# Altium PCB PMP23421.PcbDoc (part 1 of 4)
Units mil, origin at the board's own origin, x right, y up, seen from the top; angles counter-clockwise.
Board outline 2755.91 x 7559.06 mil, 8 copper layers (Top Layer, Signal Layer 1, Signal Layer 2, Signal Layer 3, Signal Layer 4, Signal Layer 5, Signal Layer 6, Bottom Layer), stack 60.4 mil thick; 211 components, 135 nets, 708 pads, 652 vias.
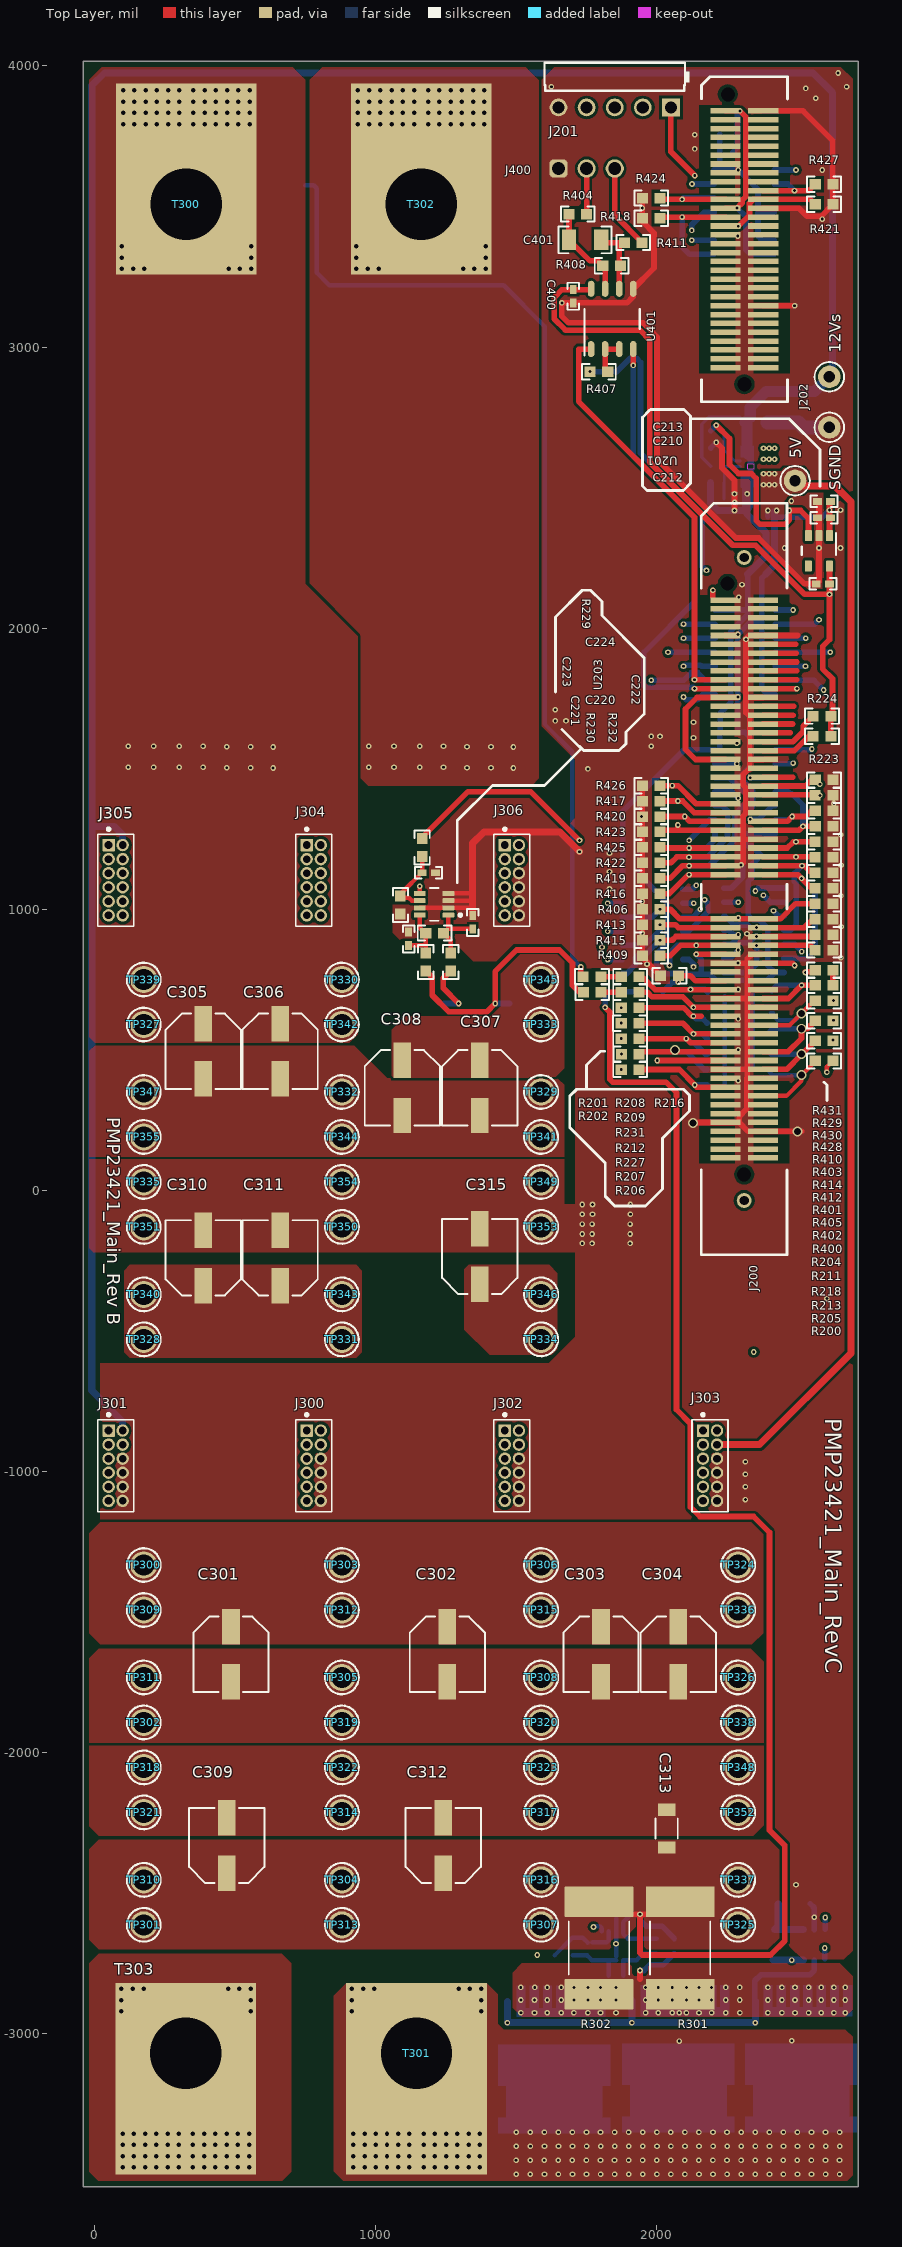
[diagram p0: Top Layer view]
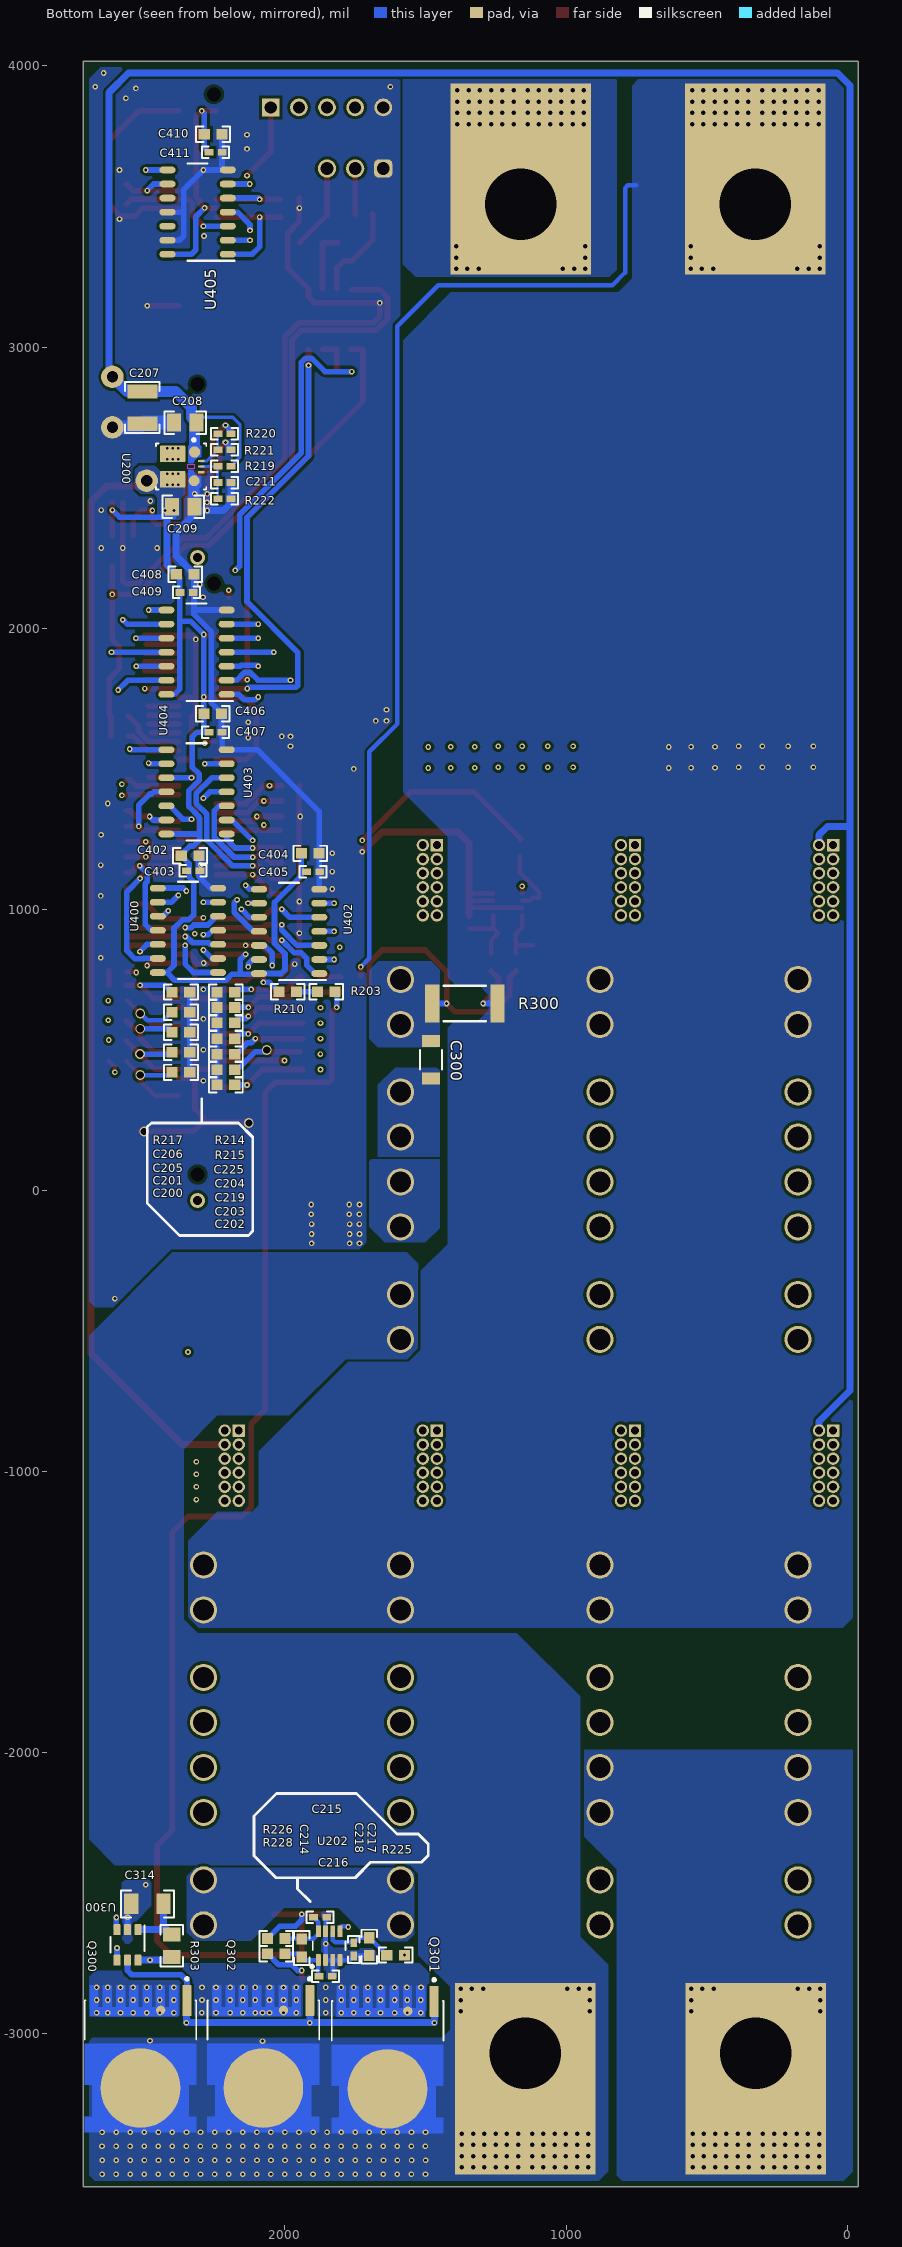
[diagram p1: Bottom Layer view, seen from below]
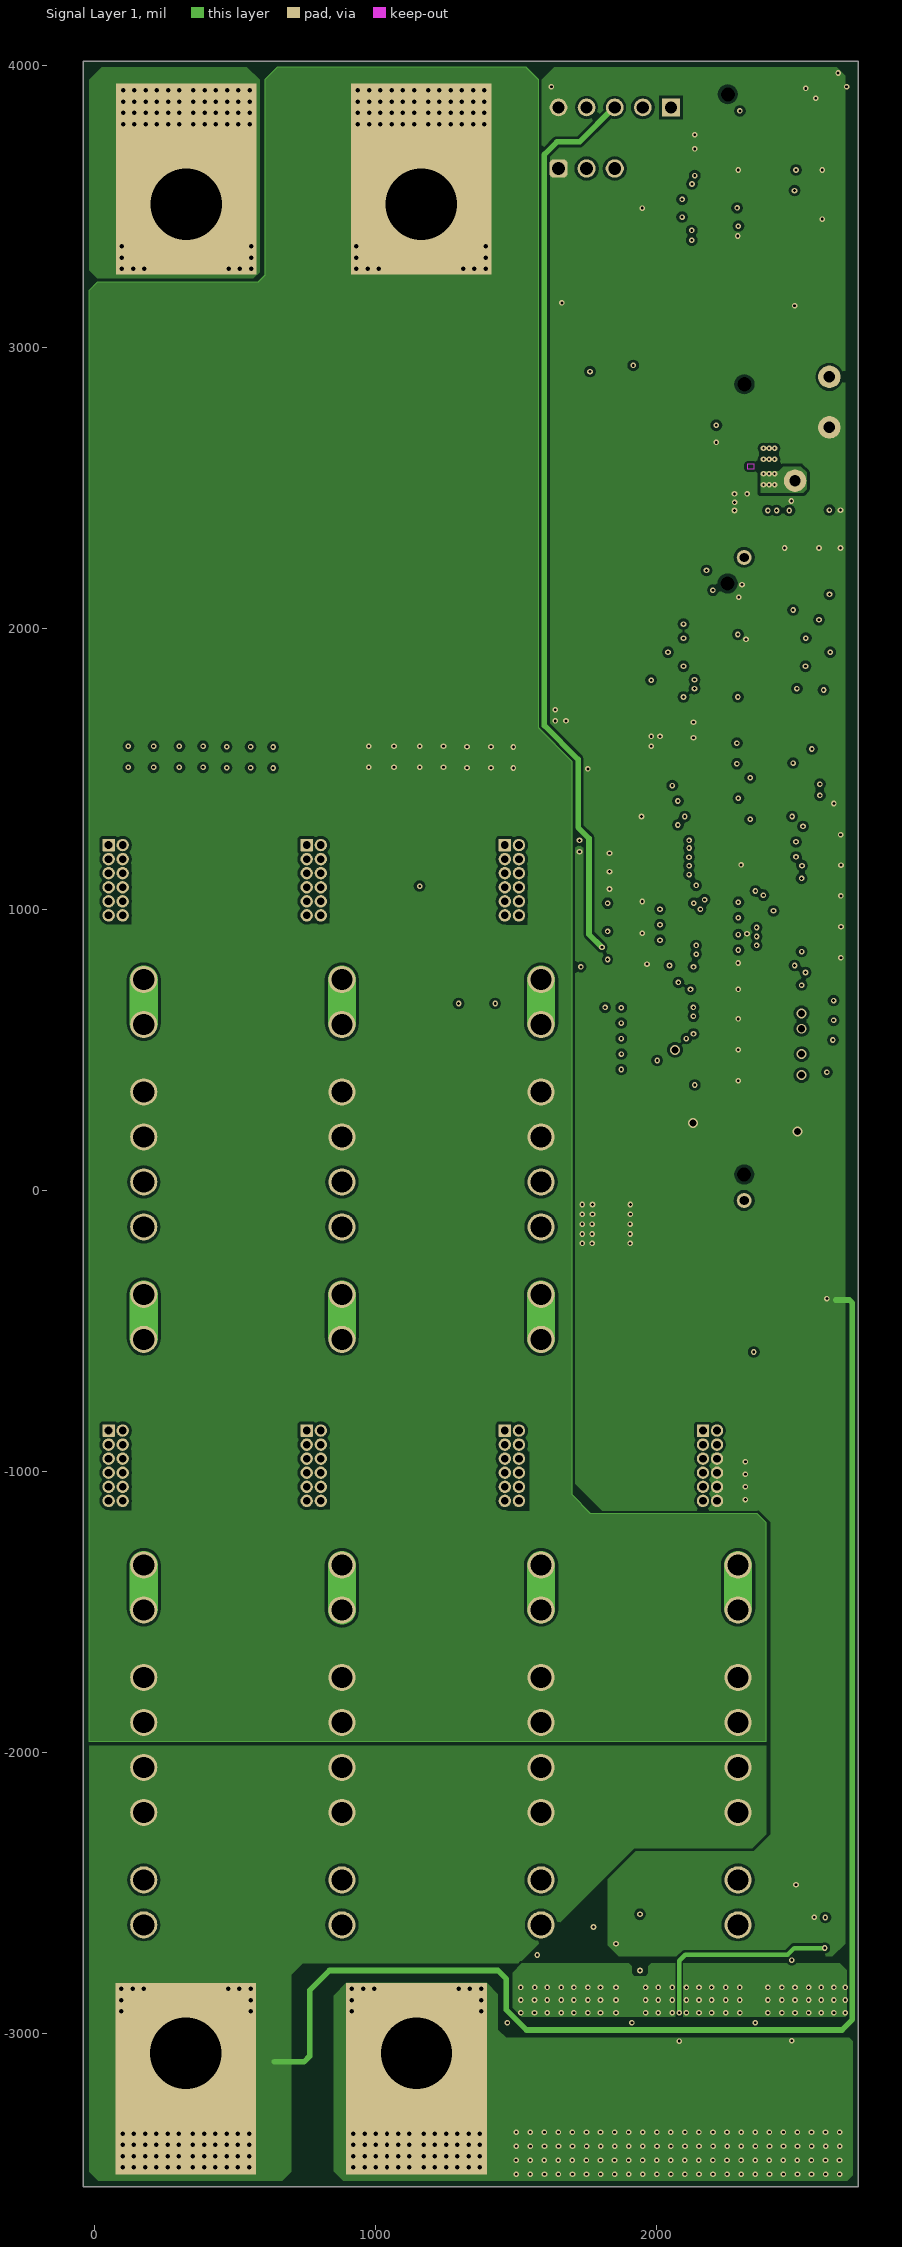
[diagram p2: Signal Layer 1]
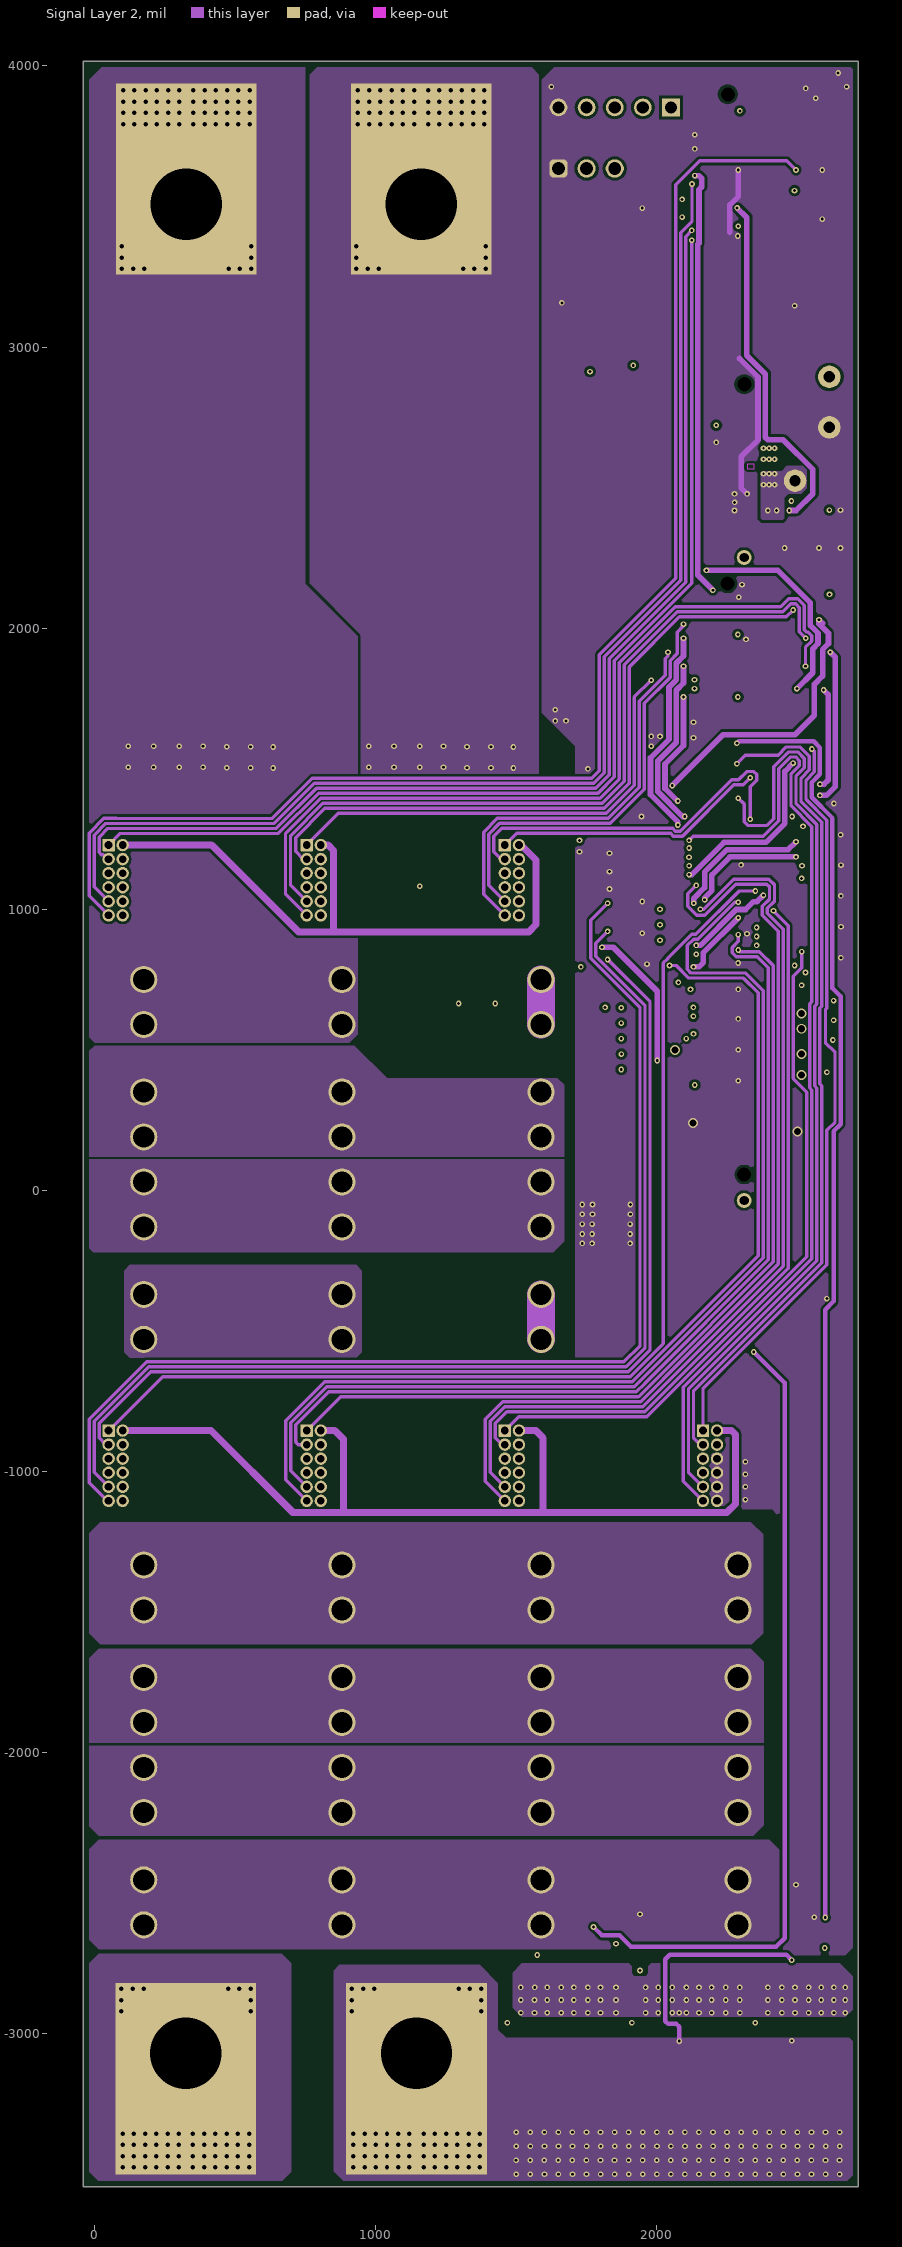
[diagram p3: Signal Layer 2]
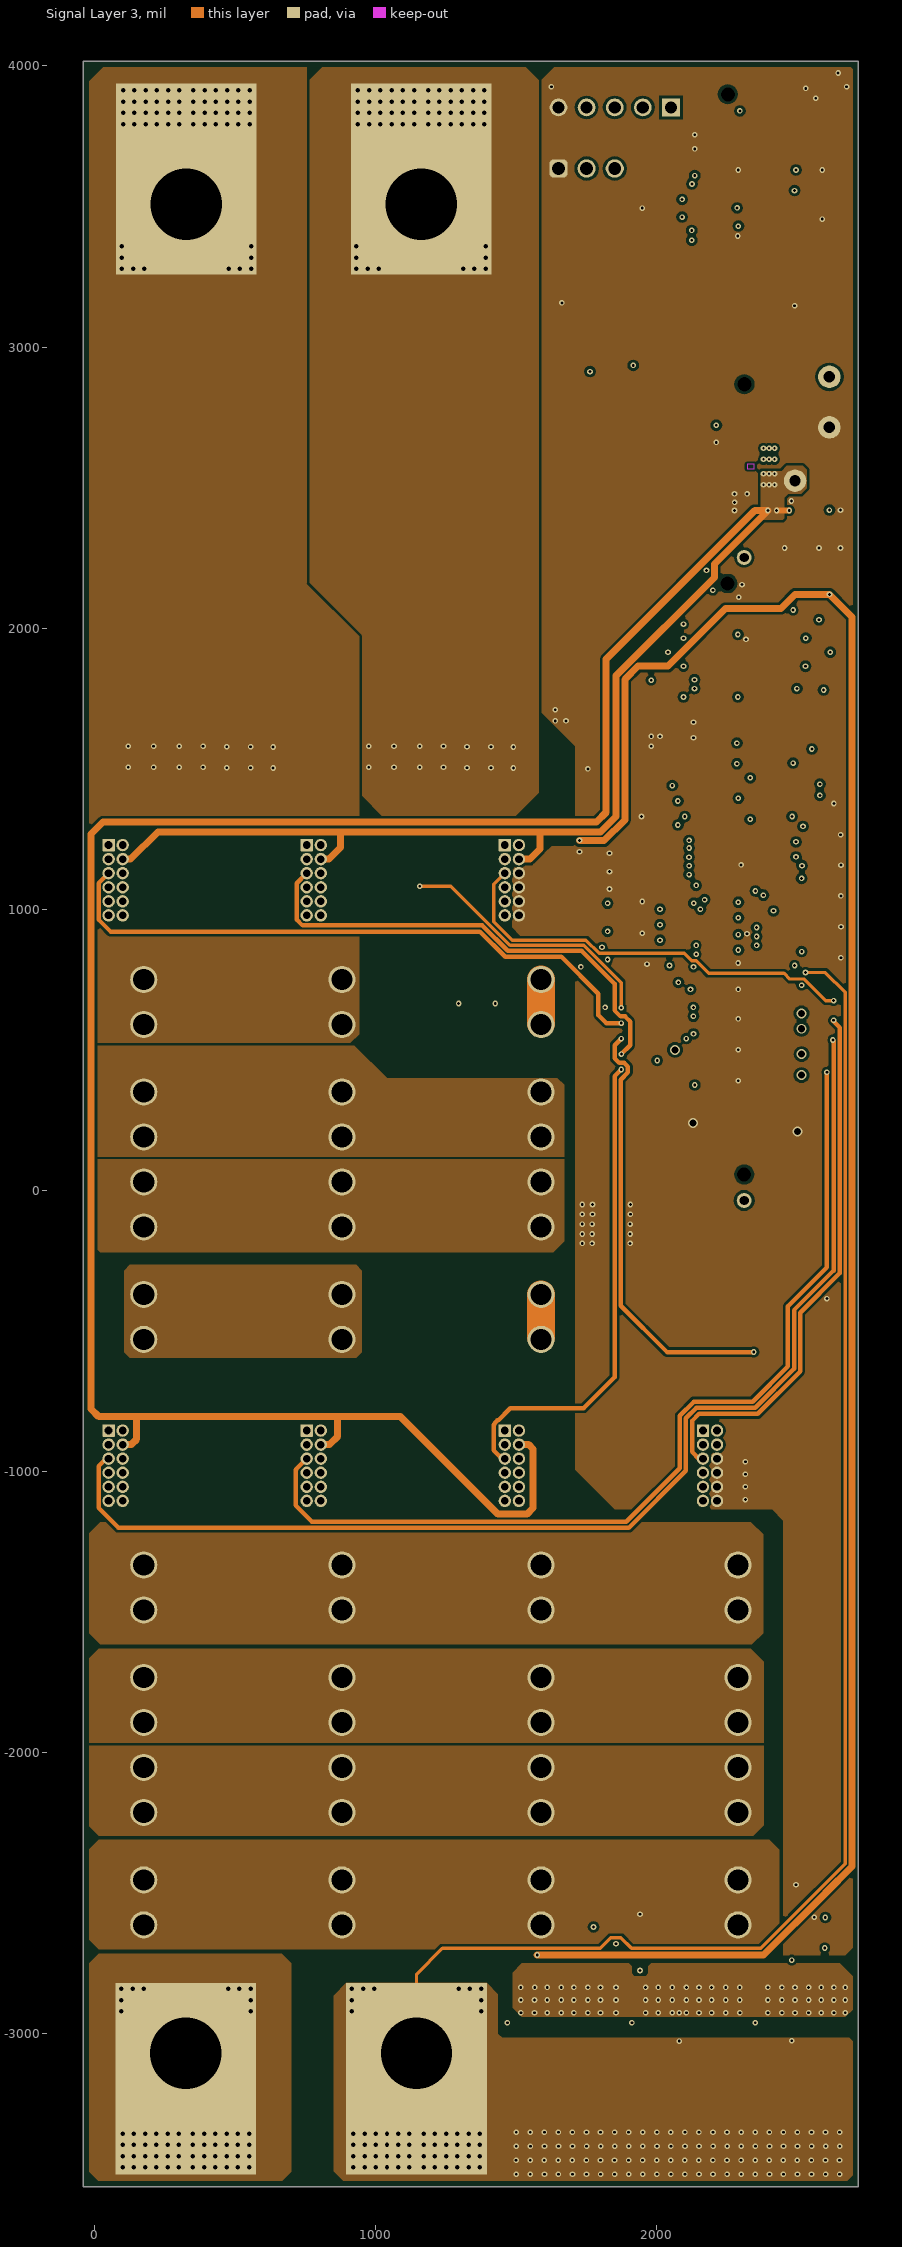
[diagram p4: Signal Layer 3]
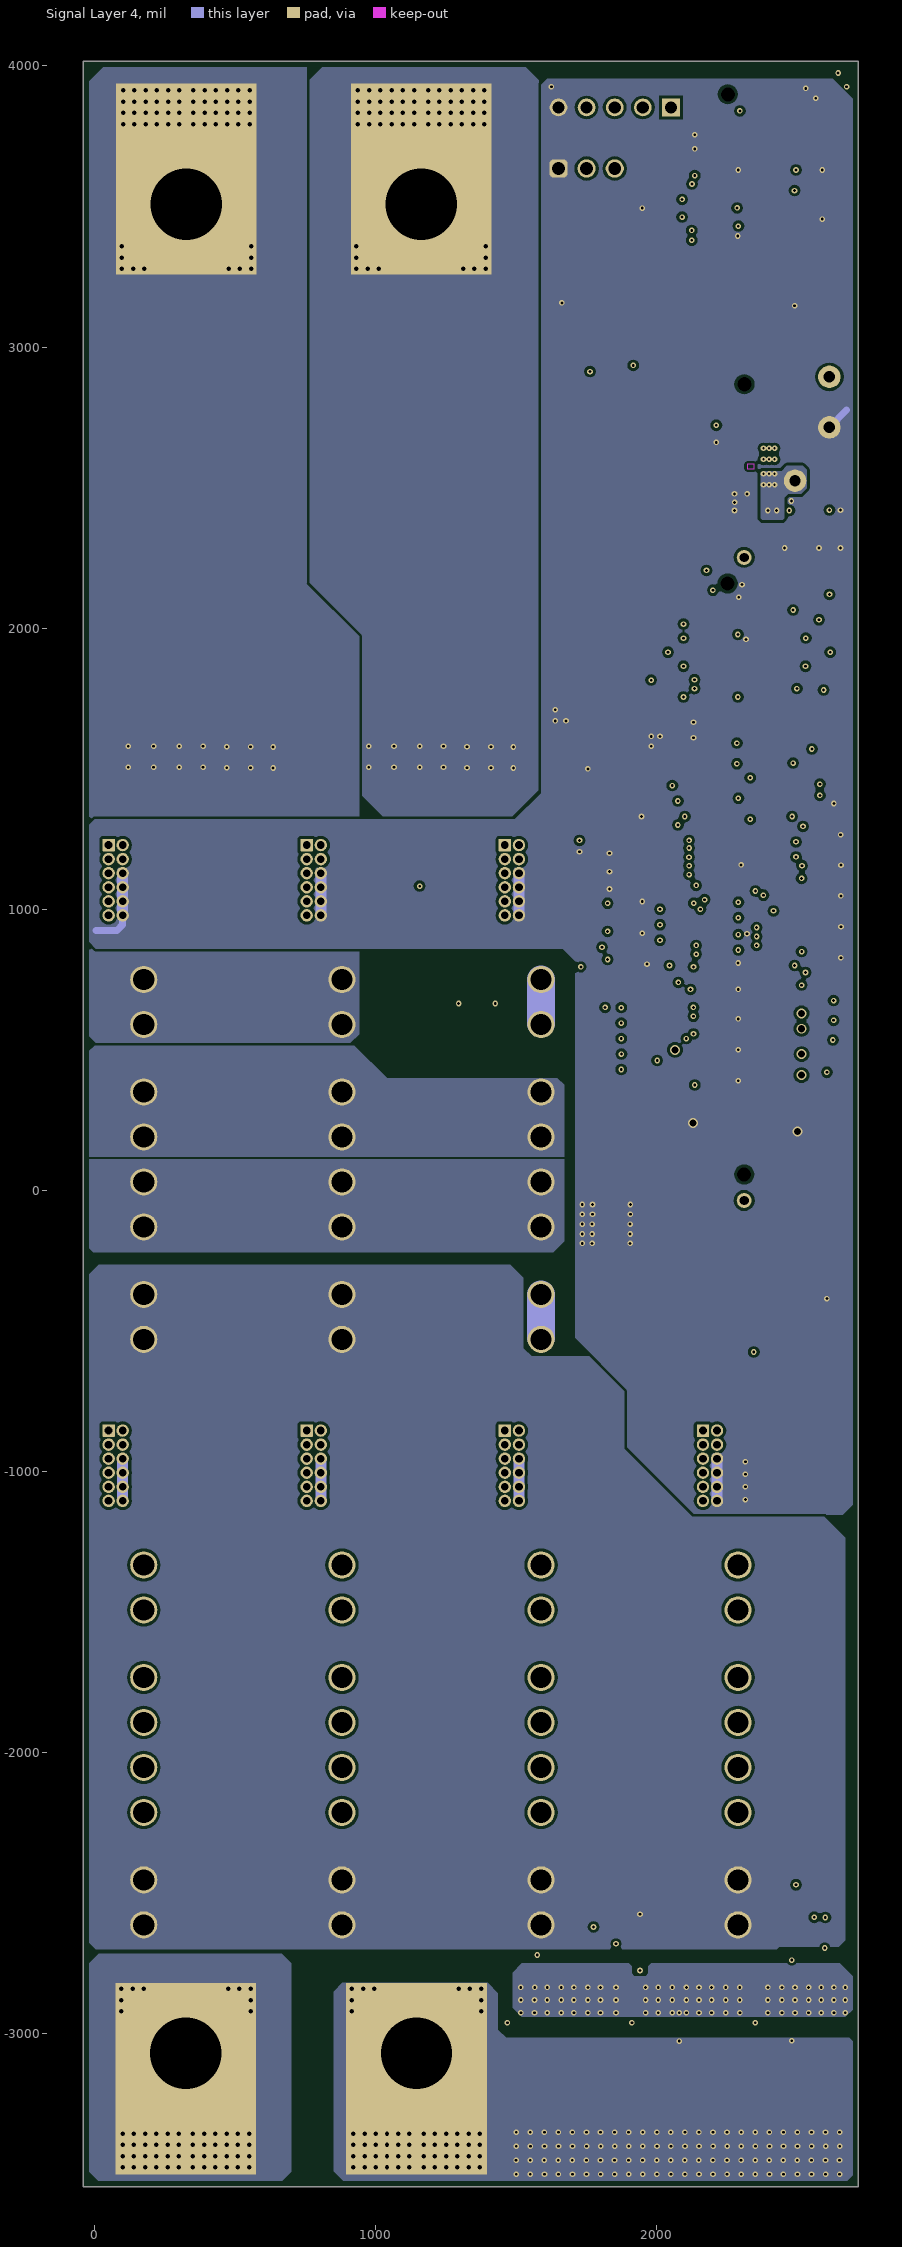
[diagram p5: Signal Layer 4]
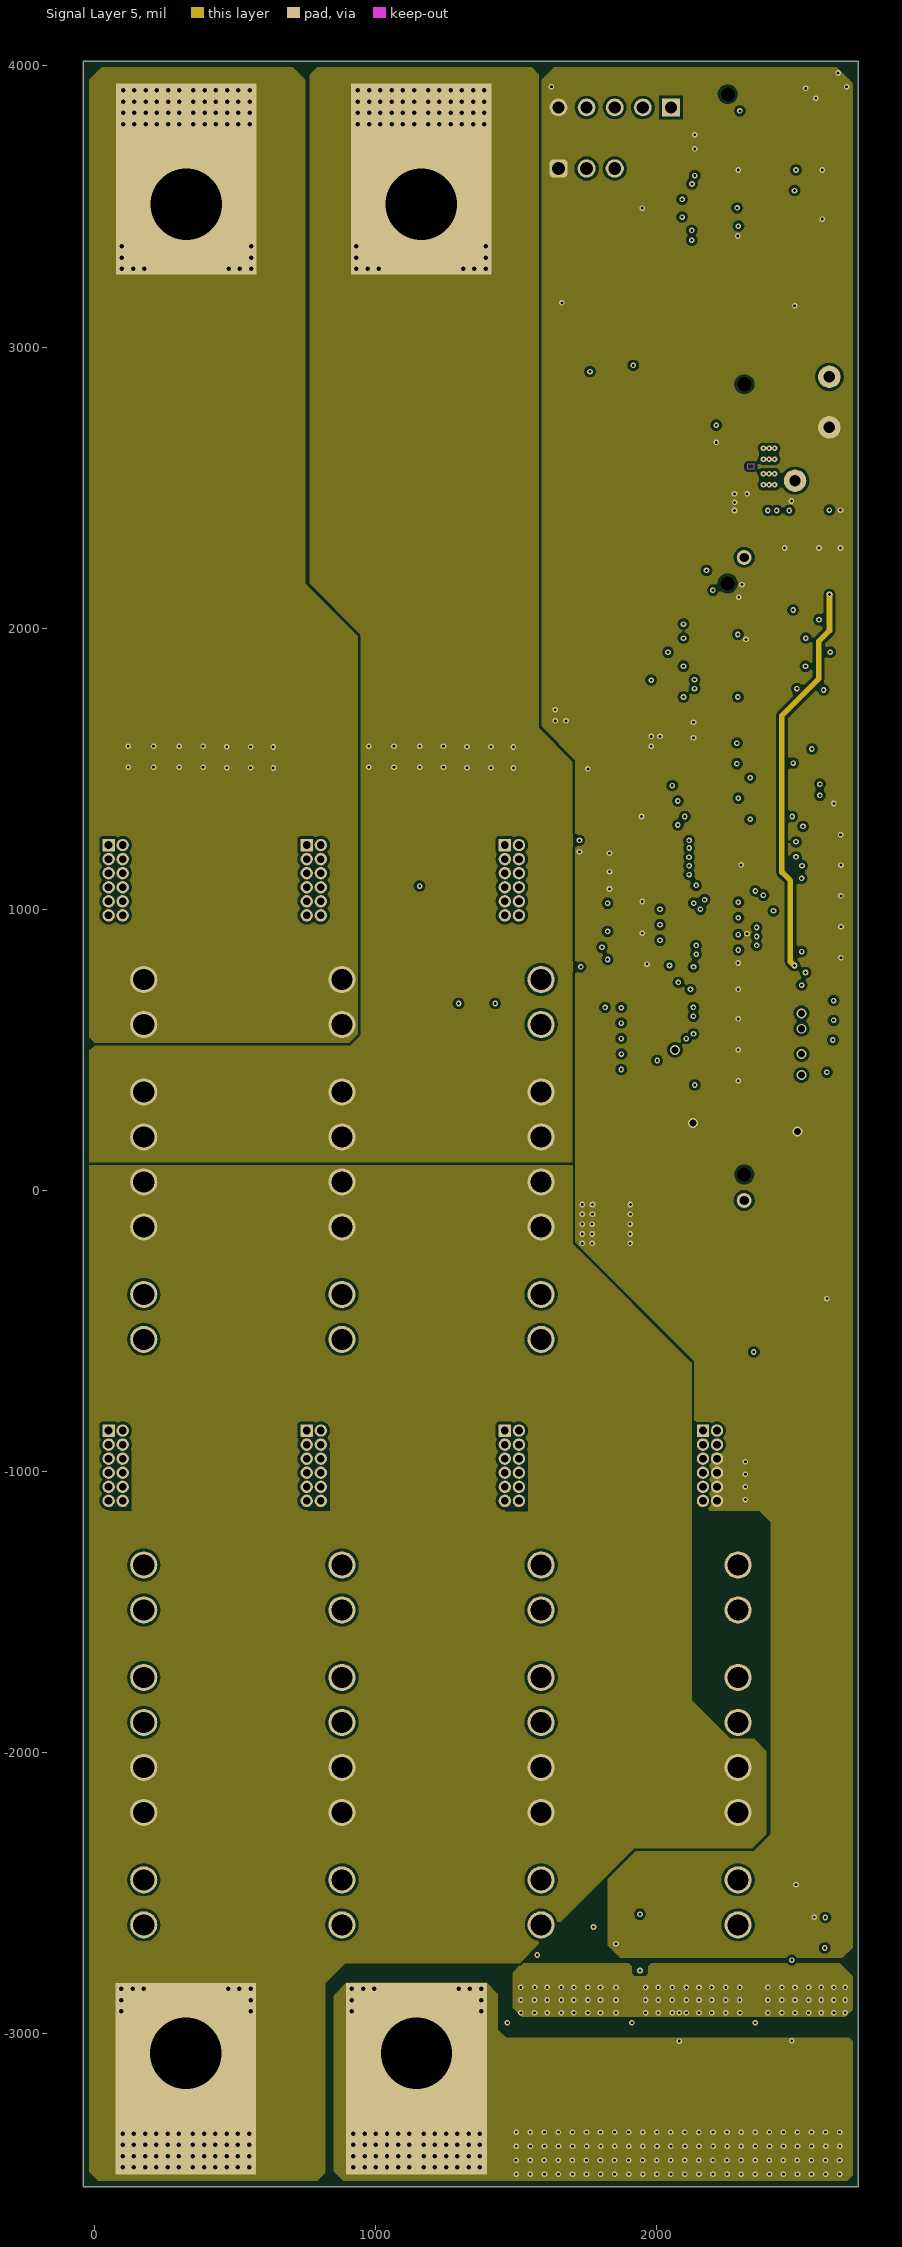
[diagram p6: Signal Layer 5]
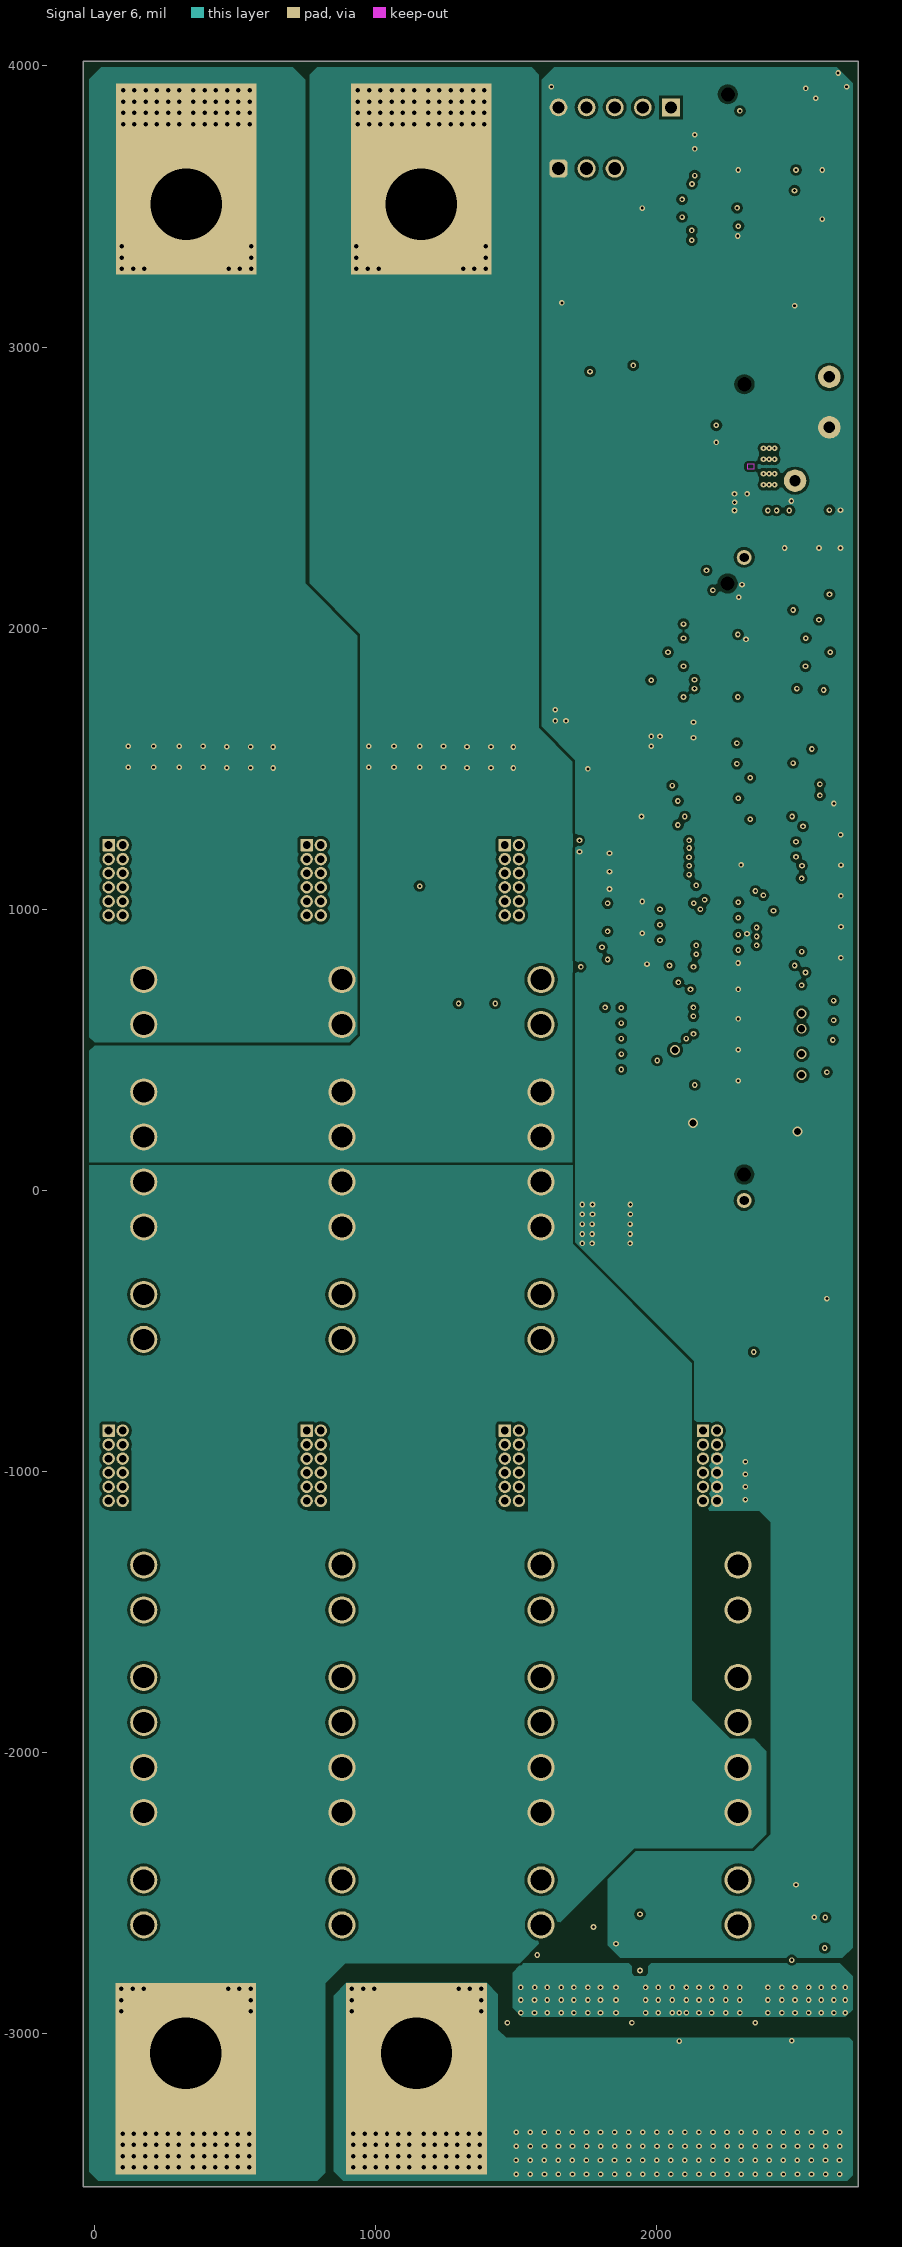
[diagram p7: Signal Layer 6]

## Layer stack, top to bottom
Top Solder: solder mask 0.394, Solder Resist, Dk 3.5
Top Layer: signal copper 2.8
Dielectric1: prepreg 5, FR-4, Dk 4.2
Signal Layer 1: signal copper 2.8
Dielectric 2: core 6, FR-4, Dk 4.2
Signal Layer 2: signal copper 2.8
Dielectric 3: prepreg 5, Dk 4.2
Signal Layer 3: signal copper 2.8
Dielectric 4: core 6, Dk 4.2
Signal Layer 4: signal copper 2.8
Dielectric 6: prepreg 5, Dk 4.2
Signal Layer 5: signal copper 2.8
Dielectric 7: core 6, Dk 4.2
Signal Layer 6: signal copper 2.8
Dielectric 5: prepreg 5, Dk 4.2
Bottom Layer: signal copper 2.8
Bottom Solder: solder mask 0.394, Solder Resist, Dk 3.5

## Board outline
-39.37,-3543.31 2716.54,-3543.31 2716.54,4015.75 -39.37,4015.75

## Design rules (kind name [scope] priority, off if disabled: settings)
AcuteAngle [All] p1: minimum=4.50000000000000E+0001 checktracksonly=FALSE
AssemblyTestPointUsage [All] p1: valid=2
BoardOutlineClearance BoardOutlineClearance_MountingHoles [OnCopper and InComponentClass('Mounting Holes')] p1: gap=40 ignorepadtopadclearanceinfootprint=FALSE
BoardOutlineClearance BoardOutlineClearance_Poly [OnCopper and IsPoly] p2: gap=20 ignorepadtopadclearanceinfootprint=FALSE
BoardOutlineClearance [OnCopper and Not InComponentClass('Logo') and not InComponentClass('FiducialMark') and not InRegion(1000,500,4000,800) and not InPoly] p3: gap=10 ignorepadtopadclearanceinfootprint=FALSE
Clearance Clearance_1 [InNetClass('HV') vs Not InNetClass('HV')] p1: gap=20 ignorepadtopadclearanceinfootprint=FALSE
Clearance Clearance_Keepouts [((IsTrack Or IsArc) And Not InPoly) And IsFree and IsKeepOut vs ((IsTrack Or IsArc) And Not InPoly) And IsFree and IsKeepOut] p2: gap=0 ignorepadtopadclearanceinfootprint=FALSE
Clearance Clearance_Poly [InPolygon] p3: gap=10 ignorepadtopadclearanceinfootprint=FALSE
Clearance Clearance_FiducialMark [IsKeepOut and InComponentClass('FiducialMark') vs IsPad and InComponentClass('FiducialMark')] p4: gap=0 ignorepadtopadclearanceinfootprint=FALSE
Clearance [All] p5: gap=5.8 ignorepadtopadclearanceinfootprint=FALSE
ComponentClearance ComponentClearance_MountingHoles_FiducialMarks [InComponentClass('Mounting Holes') vs InComponentClass('FiducialMark')] p1: gap=50 collisioncheckmode=3 verticalgap=10 showdistances=FALSE
ComponentClearance ComponentClearance_Shunt [InComponentClass('Header') vs InComponentClass('Shunt')] p2: gap=0 collisioncheckmode=3 verticalgap=0 showdistances=FALSE
ComponentClearance ComponentClearance_Logo [InComponentClass('Logo')] p3: gap=50 collisioncheckmode=3 verticalgap=10 showdistances=FALSE
ComponentClearance ComponentClearance_ScrewToNut [(HasFootprint('NY PMS 440 0025 PH')) vs (HasFootprint('Keystone_1902C'))] p4: gap=5 collisioncheckmode=3 verticalgap=10 showdistances=FALSE
ComponentClearance ComponentClearance_MountingHoles [InComponentClass('Mounting Holes')] p5: gap=250 collisioncheckmode=3 verticalgap=100000 showdistances=FALSE
ComponentClearance ComponentClearance_SmallPassives [HasFootprint('0201*') or HasFootprint('0402*') or HasFootprint('0508') or HasFootprint('0603*') or HasFootprint('0612') or HasFootprint('0805*') or HasFootprint('0815*') or HasFootprint('0830*') or HasFootprint('1206*') or HasFootprint('1210*') or HasFootprint('1808*') or HasFootprint('1812*') or HasFootprint('1825*') or HasFootprint('2010*') or HasFootprint('2220*') or HasFootprint('2225*') or HasFootprint('2512*') or HasFootprint('2728*') or HasFootprint('3518*') vs HasFootprint('0201*') or HasFootprint('0402*') or HasFootprint('0508') or HasFootprint('0603*') or HasFootprint('0612') or HasFootprint('0805*') or HasFootprint('0815*') or HasFootprint('0830*') or HasFootprint('1206*') or HasFootprint('1210*') or HasFootprint('1808*') or HasFootprint('1812*') or HasFootprint('1825*') or HasFootprint('2010*') or HasFootprint('2220*') or HasFootprint('2225*') or HasFootprint('2512*') or HasFootprint('2728*') or HasFootprint('3518*')] p6: gap=10 collisioncheckmode=3 verticalgap=10 showdistances=FALSE
ComponentClearance ComponentClearance_THtoSMT [IsThruComponent vs IsSMTComponent] p7: gap=20 collisioncheckmode=3 verticalgap=30 showdistances=FALSE
ComponentClearance ComponentClearance_THtoTH [IsThruComponent vs IsThruComponent] p8: gap=20 collisioncheckmode=3 verticalgap=20 showdistances=FALSE
ComponentClearance [All] p9: gap=5.5 collisioncheckmode=3 verticalgap=5.5 showdistances=FALSE
DiffPairsRouting [All] p1: maxlimit=100 minlimit=10 mostfreqgap=10 toplayer_minwidth=15 toplayer_maxwidth=15 toplayer_prefwidth=15 midlayer1_minwidth=15 midlayer1_maxwidth=15 midlayer1_prefwidth=15 midlayer2_minwidth=15 midlayer2_maxwidth=15 midlayer2_prefwidth=15 midlayer3_minwidth=15 midlayer3_maxwidth=15 midlayer3_prefwidth=15 midlayer4_minwidth=15 midlayer4_maxwidth=15 midlayer4_prefwidth=15 midlayer5_minwidth=15 midlayer5_maxwidth=15 midlayer5_prefwidth=15 midlayer6_minwidth=15 midlayer6_maxwidth=15 midlayer6_prefwidth=15 bottomlayer_minwidth=15 bottomlayer_maxwidth=15 bottomlayer_prefwidth=15 maxuncoupledlength=1000
FabricationTestPointUsage TestPointUsage [All] p1: valid=2 allowmultiple=FALSE
FabricationTestpoint Testpoint [All] p1: side=3 testpointundercomponent=TRUE minsize=40 maxsize=100 preferedsize=60 minholesize=0 maxholesize=40 preferedholesize=32 testpointgrid=1 allowsidetop=TRUE allowsidebottom=TRUE usegrid=TRUE gridtolerance=0.01
FanoutControl Fanout_LCC [IsLCC] p1: bgadir=Out bgaviamode=Centered fanoutstyle=Auto fanoutdirection=Alternating viagrid=1 // Fanout_LCC (Default Rule)
FanoutControl Fanout_BGA [IsBGA] p2: bgadir=Out bgaviamode=Centered fanoutstyle=Auto fanoutdirection=Alternating viagrid=1 // Fanout_BGA (Default Rule)
FanoutControl Fanout_Default [All] p4: bgadir=Out bgaviamode=Centered fanoutstyle=Auto fanoutdirection=Alternating viagrid=1 // Fanout_Default (Default Rule)
FanoutControl Fanout_Small [(CompPinCount < 5)] p5: bgadir=Out bgaviamode=Centered fanoutstyle=Auto fanoutdirection=OutThenIn viagrid=1 // Fanout_Small (Default Rule)
HoleSize [All] p1: absolutevalues=TRUE maxlimit=260 minlimit=7.87 maxpercent=80.000 minpercent=20.000
MinimumAnnularRing MinimumAnnularRing_ThermalPadVias [IsVia and InAnyComponent] p1: minimumring=5.91
MinimumAnnularRing [All] p2: minimumring=5
MinimumSolderMaskSliver MinimumSolderMaskSliver_Logo [InComponentClass('Logo') vs InComponentClass('Logo')] p1: minsoldermaskwidth=0.7
MinimumSolderMaskSliver [All] p2: minsoldermaskwidth=3
PlaneConnect [All] p1: planeconnectstyle=Relief reliefexpansion=10 reliefentries=4 reliefconductorwidth=10 reliefairgap=10
PolygonConnect PolygonConnect_32 [All vs IsNamedPolygon('5V') Or  IsNamedPolygon('CS-_total_charge_current_battery') Or  IsNamedPolygon('5V') Or  IsNamedPolygon('CS-_total_charge_current_battery') Or  IsNamedPolygon('48Vout2') Or  IsNamedPolygon('48VOUT1') Or  IsNamedPolygon('SGND') Or  IsNamedPolygon('48Vout2') Or  IsNamedPolygon('CS-_total_discharge_current_bus') Or  IsNamedPolygon('5V') Or  IsNamedPolygon('48Vout2') Or  IsNamedPolygon('5V') Or  IsNamedPolygon('5V') Or  IsNamedPolygon('VBAT-') Or  IsNamedPolygon('5V') Or  IsNamedPolygon('48Vout2') Or  IsNamedPolygon('VBAT-') Or  IsNamedPolygon('48Vout2') Or  IsNamedPolygon('5V') Or  IsNamedPolygon('5V') Or  IsNamedPolygon('48Vout2') Or  IsNamedPolygon('5V') Or  IsNamedPolygon('CS-_total_charge_current_battery') Or  IsNamedPolygon('SGND') Or  IsNamedPolygon('SGND') Or  IsNamedPolygon('SGND') Or  IsNamedPolygon('CS-_total_discharge_current_bus') Or  IsNamedPolygon('SGND') Or  IsNamedPolygon('SGND') Or  IsNamedPolygon('CS-_total_charge_current_battery') Or  IsNamedPolygon('SGND') Or  IsNamedPolygon('48Vout1') Or  IsNamedPolygon('SGND') Or  IsNamedPolygon('CS-_total_charge_current_battery') Or  IsNamedPolygon('SGND') Or  IsNamedPolygon('VBAT-') Or  IsNamedPolygon('CS-_total_discharge_current_bus') Or  IsNamedPolygon('VBAT-') Or  IsNamedPolygon('VBAT-') Or  IsNamedPolygon('VBAT-') Or  IsNamedPolygon('CS-_total_discharge_current_bus') Or  IsNamedPolygon('SGND') Or  IsNamedPolygon('48Vout2') Or  IsNamedPolygon('VBAT-') Or  IsNamedPolygon('48Vout2') Or  IsNamedPolygon('VBAT-') Or  IsNamedPolygon('CS-') Or  IsNamedPolygon('SGND') Or  IsNamedPolygon('VBAT-') Or  IsNamedPolygon('SGND') Or  IsNamedPolygon('VBAT-') Or  IsNamedPolygon('48Vout1') Or  IsNamedPolygon('VBAT-') Or  IsNamedPolygon('CS-') Or  IsNamedPolygon('SGND') Or  IsNamedPolygon('48Vout1') Or  IsNamedPolygon('SGND') Or  IsNamedPolygon('VBAT-') Or  IsNamedPolygon('SGND') Or  IsNamedPolygon('CS-_total_charge_current_battery') Or  IsNamedPolygon('CS-_total_charge_current_battery') Or  IsNamedPolygon('VBAT-') Or  IsNamedPolygon('CS-_total_discharge_current_bus') Or  IsNamedPolygon('SGND') Or  IsNamedPolygon('CS-_total_charge_current_battery') Or  IsNamedPolygon('CS+_total_charge_current_battery') Or  IsNamedPolygon('48Vout1') Or  IsNamedPolygon('VBAT-') Or  IsNamedPolygon('SGND') Or  IsNamedPolygon('CS-_total_discharge_current_bus') Or  IsNamedPolygon('CS-_total_discharge_current_bus') Or  IsNamedPolygon('48Vout1') Or  IsNamedPolygon('SGND') Or  IsNamedPolygon('SGND') Or  IsNamedPolygon('CS-_total_charge_current_battery') Or  IsNamedPolygon('SGND') Or  IsNamedPolygon('VBAT-') Or  IsNamedPolygon('SGND') Or  IsNamedPolygon('SGND') Or  IsNamedPolygon('SGND') Or  IsNamedPolygon('VBAT-') Or  IsNamedPolygon('48Vout2') Or  IsNamedPolygon('VBAT-') Or  IsNamedPolygon('CS-_total_charge_current_battery') Or  IsNamedPolygon('CS-_total_charge_current_battery') Or  IsNamedPolygon('48Vout1') Or  IsNamedPolygon('SGND') Or  IsNamedPolygon('SGND') Or  IsNamedPolygon('CS+_total_charge_current_battery') Or  IsNamedPolygon('CS-_total_discharge_current_bus') Or  IsNamedPolygon('SGND') Or  IsNamedPolygon('48Vout1') Or  IsNamedPolygon('CS-_total_discharge_current_bus') Or  IsNamedPolygon('48V2') Or  IsNamedPolygon('CS-')] p1: connectstyle=Direct reliefconductorwidth=10 reliefentries=4 polygonreliefangle="90 Angle" airgapwidth=10
PolygonConnect PolygonConnect_31 [All vs IsNamedPolygon('CS-_total_charge_current_battery') Or  IsNamedPolygon('5V') Or  IsNamedPolygon('5V') Or  IsNamedPolygon('48Vout2') Or  IsNamedPolygon('CS-_total_discharge_current_bus') Or  IsNamedPolygon('5V') Or  IsNamedPolygon('VBAT-') Or  IsNamedPolygon('48Vout2') Or  IsNamedPolygon('5V') Or  IsNamedPolygon('5V') Or  IsNamedPolygon('CS-_total_charge_current_battery') Or  IsNamedPolygon('48Vout2') Or  IsNamedPolygon('VBAT-') Or  IsNamedPolygon('5V') Or  IsNamedPolygon('48Vout2') Or  IsNamedPolygon('5V') Or  IsNamedPolygon('48Vout2') Or  IsNamedPolygon('48Vout2') Or  IsNamedPolygon('VBAT-') Or  IsNamedPolygon('VBAT-') Or  IsNamedPolygon('VBAT-') Or  IsNamedPolygon('48Vout1') Or  IsNamedPolygon('VBAT-') Or  IsNamedPolygon('48Vout1') Or  IsNamedPolygon('48Vout1') Or  IsNamedPolygon('VBAT-') Or  IsNamedPolygon('CS-_total_charge_current_battery') Or  IsNamedPolygon('CS-_total_discharge_current_bus') Or  IsNamedPolygon('CS-') Or  IsNamedPolygon('48Vout2') Or  IsNamedPolygon('CS-_total_charge_current_battery') Or  IsNamedPolygon('VBAT-') Or  IsNamedPolygon('CS+_total_charge_current_battery') Or  IsNamedPolygon('VBAT-') Or  IsNamedPolygon('CS-_total_charge_current_battery') Or  IsNamedPolygon('VBAT-') Or  IsNamedPolygon('48Vout2') Or  IsNamedPolygon('VBAT-') Or  IsNamedPolygon('VBAT-') Or  IsNamedPolygon('CS-') Or  IsNamedPolygon('CS-_total_discharge_current_bus') Or  IsNamedPolygon('CS-_total_discharge_current_bus') Or  IsNamedPolygon('CS-_total_charge_current_battery') Or  IsNamedPolygon('VBAT-') Or  IsNamedPolygon('VBAT-') Or  IsNamedPolygon('VBAT-') Or  IsNamedPolygon('VBAT-') Or  IsNamedPolygon('VBAT-') Or  IsNamedPolygon('VBAT-') Or  IsNamedPolygon('VBAT-') Or  IsNamedPolygon('CS-_total_charge_current_battery') Or  IsNamedPolygon('VBAT-') Or  IsNamedPolygon('VBAT-') Or  IsNamedPolygon('VBAT-') Or  IsNamedPolygon('VBAT-') Or  IsNamedPolygon('CS-_total_discharge_current_bus') Or  IsNamedPolygon('48V2') Or  IsNamedPolygon('5V') Or  IsNamedPolygon('CS-_total_discharge_current_bus') Or  IsNamedPolygon('48Vout1') Or  IsNamedPolygon('48Vout1') Or  IsNamedPolygon('VBAT-') Or  IsNamedPolygon('VBAT-') Or  IsNamedPolygon('CS-_total_charge_current_battery') Or  IsNamedPolygon('VBAT-') Or  IsNamedPolygon('VBAT-') Or  IsNamedPolygon('CS-_total_discharge_current_bus') Or  IsNamedPolygon('VBAT-') Or  IsNamedPolygon('VBAT-') Or  IsNamedPolygon('CS-_total_discharge_current_bus') Or  IsNamedPolygon('CS-') Or  IsNamedPolygon('48VOUT1') Or  IsNamedPolygon('VBAT-') Or  IsNamedPolygon('48Vout1') Or  IsNamedPolygon('5V') Or  IsNamedPolygon('48Vout1') Or  IsNamedPolygon('VBAT-') Or  IsNamedPolygon('VBAT-') Or  IsNamedPolygon('CS-_total_charge_current_battery') Or  IsNamedPolygon('VBAT-') Or  IsNamedPolygon('VBAT-') Or  IsNamedPolygon('VBAT-') Or  IsNamedPolygon('VBAT-') Or  IsNamedPolygon('VBAT-') Or  IsNamedPolygon('CS+_total_charge_current_battery') Or  IsNamedPolygon('VBAT-')] p2: connectstyle=Direct reliefconductorwidth=10 reliefentries=4 polygonreliefangle="90 Angle" airgapwidth=10
PolygonConnect PolygonConnect_30 [All vs IsNamedPolygon('48Vout2') Or  IsNamedPolygon('VBAT-') Or  IsNamedPolygon('VBAT-') Or  IsNamedPolygon('CS-_total_charge_current_battery') Or  IsNamedPolygon('48Vout1') Or  IsNamedPolygon('5V') Or  IsNamedPolygon('VBAT-') Or  IsNamedPolygon('48Vout2') Or  IsNamedPolygon('VBAT-') Or  IsNamedPolygon('CS-_total_discharge_current_bus') Or  IsNamedPolygon('CS+_total_charge_current_battery') Or  IsNamedPolygon('VBAT-') Or  IsNamedPolygon('CS-_total_charge_current_battery') Or  IsNamedPolygon('48VOUT1') Or  IsNamedPolygon('VBAT-') Or  IsNamedPolygon('VBAT-') Or  IsNamedPolygon('CS-_total_discharge_current_bus') Or  IsNamedPolygon('VBAT-') Or  IsNamedPolygon('5V') Or  IsNamedPolygon('48Vout2') Or  IsNamedPolygon('CS-_total_charge_current_battery') Or  IsNamedPolygon('VBAT-') Or  IsNamedPolygon('5V') Or  IsNamedPolygon('VBAT-') Or  IsNamedPolygon('5V') Or  IsNamedPolygon('VBAT-') Or  IsNamedPolygon('CS-_total_discharge_current_bus') Or  IsNamedPolygon('VBAT-') Or  IsNamedPolygon('48Vout1') Or  IsNamedPolygon('CS-_total_discharge_current_bus') Or  IsNamedPolygon('VBAT-') Or  IsNamedPolygon('5V') Or  IsNamedPolygon('48Vout2') Or  IsNamedPolygon('CS-') Or  IsNamedPolygon('VBAT-') Or  IsNamedPolygon('CS+_total_charge_current_battery') Or  IsNamedPolygon('VBAT-') Or  IsNamedPolygon('VBAT-') Or  IsNamedPolygon('CS-_total_charge_current_battery') Or  IsNamedPolygon('48Vout2') Or  IsNamedPolygon('VBAT-') Or  IsNamedPolygon('CS-_total_charge_current_battery') Or  IsNamedPolygon('48Vout1') Or  IsNamedPolygon('CS-_total_charge_current_battery') Or  IsNamedPolygon('48Vout2') Or  IsNamedPolygon('VBAT-') Or  IsNamedPolygon('VBAT-') Or  IsNamedPolygon('VBAT-') Or  IsNamedPolygon('VBAT-') Or  IsNamedPolygon('CS-') Or  IsNamedPolygon('48Vout1') Or  IsNamedPolygon('CS-') Or  IsNamedPolygon('CS-_total_charge_current_battery') Or  IsNamedPolygon('VBAT-') Or  IsNamedPolygon('VBAT-') Or  IsNamedPolygon('48Vout1') Or  IsNamedPolygon('CS-_total_discharge_current_bus') Or  IsNamedPolygon('VBAT-') Or  IsNamedPolygon('VBAT-') Or  IsNamedPolygon('VBAT-') Or  IsNamedPolygon('CS-_total_discharge_current_bus') Or  IsNamedPolygon('5V') Or  IsNamedPolygon('48Vout2') Or  IsNamedPolygon('VBAT-') Or  IsNamedPolygon('VBAT-') Or  IsNamedPolygon('VBAT-') Or  IsNamedPolygon('48Vout1') Or  IsNamedPolygon('VBAT-') Or  IsNamedPolygon('5V') Or  IsNamedPolygon('VBAT-') Or  IsNamedPolygon('VBAT-') Or  IsNamedPolygon('VBAT-') Or  IsNamedPolygon('5V') Or  IsNamedPolygon('48V2') Or  IsNamedPolygon('CS-_total_discharge_current_bus') Or  IsNamedPolygon('VBAT-') Or  IsNamedPolygon('VBAT-') Or  IsNamedPolygon('CS-_total_charge_current_battery') Or  IsNamedPolygon('48Vout1') Or  IsNamedPolygon('VBAT-') Or  IsNamedPolygon('CS-_total_charge_current_battery') Or  IsNamedPolygon('5V')] p3: connectstyle=Direct reliefconductorwidth=10 reliefentries=4 polygonreliefangle="90 Angle" airgapwidth=10
PolygonConnect PolygonConnect_29 [All vs IsNamedPolygon('CS-_total_charge_current_battery') Or  IsNamedPolygon('CS-_total_discharge_current_bus') Or  IsNamedPolygon('5V') Or  IsNamedPolygon('48Vout1') Or  IsNamedPolygon('VBAT-') Or  IsNamedPolygon('5V') Or  IsNamedPolygon('VBAT-') Or  IsNamedPolygon('48Vout2') Or  IsNamedPolygon('VBAT-') Or  IsNamedPolygon('48Vout2') Or  IsNamedPolygon('CS-_total_charge_current_battery') Or  IsNamedPolygon('VBAT-') Or  IsNamedPolygon('48Vout1') Or  IsNamedPolygon('48Vout1') Or  IsNamedPolygon('48Vout1') Or  IsNamedPolygon('VBAT-') Or  IsNamedPolygon('48VOUT1') Or  IsNamedPolygon('5V') Or  IsNamedPolygon('CS-_total_discharge_current_bus') Or  IsNamedPolygon('5V') Or  IsNamedPolygon('VBAT-') Or  IsNamedPolygon('VBAT-') Or  IsNamedPolygon('5V') Or  IsNamedPolygon('VBAT-') Or  IsNamedPolygon('VBAT-') Or  IsNamedPolygon('VBAT-') Or  IsNamedPolygon('CS-') Or  IsNamedPolygon('5V') Or  IsNamedPolygon('VBAT-') Or  IsNamedPolygon('5V') Or  IsNamedPolygon('VBAT-') Or  IsNamedPolygon('48Vout1') Or  IsNamedPolygon('CS+_total_charge_current_battery') Or  IsNamedPolygon('VBAT-') Or  IsNamedPolygon('VBAT-') Or  IsNamedPolygon('CS-_total_charge_current_battery') Or  IsNamedPolygon('5V') Or  IsNamedPolygon('VBAT-') Or  IsNamedPolygon('48Vout1') Or  IsNamedPolygon('CS-_total_charge_current_battery') Or  IsNamedPolygon('VBAT-') Or  IsNamedPolygon('CS-') Or  IsNamedPolygon('5V') Or  IsNamedPolygon('48Vout2') Or  IsNamedPolygon('CS-_total_charge_current_battery') Or  IsNamedPolygon('VBAT-') Or  IsNamedPolygon('48Vout2') Or  IsNamedPolygon('VBAT-') Or  IsNamedPolygon('48Vout2') Or  IsNamedPolygon('CS-') Or  IsNamedPolygon('VBAT-') Or  IsNamedPolygon('VBAT-') Or  IsNamedPolygon('48V2') Or  IsNamedPolygon('CS+_total_charge_current_battery') Or  IsNamedPolygon('VBAT-') Or  IsNamedPolygon('VBAT-') Or  IsNamedPolygon('VBAT-') Or  IsNamedPolygon('CS-_total_charge_current_battery') Or  IsNamedPolygon('CS-_total_discharge_current_bus') Or  IsNamedPolygon('48Vout2') Or  IsNamedPolygon('CS-_total_discharge_current_bus') Or  IsNamedPolygon('CS-_total_discharge_current_bus') Or  IsNamedPolygon('VBAT-') Or  IsNamedPolygon('48Vout1') Or  IsNamedPolygon('CS-_total_charge_current_battery') Or  IsNamedPolygon('VBAT-') Or  IsNamedPolygon('CS-_total_charge_current_battery') Or  IsNamedPolygon('CS-_total_discharge_current_bus') Or  IsNamedPolygon('VBAT-') Or  IsNamedPolygon('VBAT-') Or  IsNamedPolygon('CS-_total_charge_current_battery') Or  IsNamedPolygon('48Vout2') Or  IsNamedPolygon('CS-_total_discharge_current_bus') Or  IsNamedPolygon('VBAT-')] p4: connectstyle=Direct reliefconductorwidth=10 reliefentries=4 polygonreliefangle="90 Angle" airgapwidth=10
PolygonConnect PolygonConnect_28 [All vs IsNamedPolygon('48VOUT1') Or  IsNamedPolygon('VBAT-') Or  IsNamedPolygon('VBAT-') Or  IsNamedPolygon('VBAT-') Or  IsNamedPolygon('VBAT-') Or  IsNamedPolygon('5V') Or  IsNamedPolygon('VBAT-') Or  IsNamedPolygon('VBAT-') Or  IsNamedPolygon('VBAT-') Or  IsNamedPolygon('48Vout1') Or  IsNamedPolygon('CS-_total_discharge_current_bus') Or  IsNamedPolygon('VBAT-') Or  IsNamedPolygon('VBAT-') Or  IsNamedPolygon('CS-') Or  IsNamedPolygon('VBAT-') Or  IsNamedPolygon('CS-_total_discharge_current_bus') Or  IsNamedPolygon('CS-_total_charge_current_battery') Or  IsNamedPolygon('48Vout2') Or  IsNamedPolygon('CS-_total_charge_current_battery') Or  IsNamedPolygon('VBAT-') Or  IsNamedPolygon('CS+_total_charge_current_battery') Or  IsNamedPolygon('48Vout1') Or  IsNamedPolygon('VBAT-') Or  IsNamedPolygon('CS-_total_charge_current_battery') Or  IsNamedPolygon('5V') Or  IsNamedPolygon('48Vout2') Or  IsNamedPolygon('CS-_total_discharge_current_bus') Or  IsNamedPolygon('5V') Or  IsNamedPolygon('VBAT-') Or  IsNamedPolygon('CS-_total_charge_current_battery') Or  IsNamedPolygon('VBAT-') Or  IsNamedPolygon('VBAT-') Or  IsNamedPolygon('48Vout2') Or  IsNamedPolygon('5V') Or  IsNamedPolygon('VBAT-') Or  IsNamedPolygon('5V') Or  IsNamedPolygon('CS-_total_discharge_current_bus') Or  IsNamedPolygon('VBAT-') Or  IsNamedPolygon('CS+_total_charge_current_battery') Or  IsNamedPolygon('VBAT-') Or  IsNamedPolygon('48Vout1') Or  IsNamedPolygon('VBAT-') Or  IsNamedPolygon('CS-_total_discharge_current_bus') Or  IsNamedPolygon('CS-_total_discharge_current_bus') Or  IsNamedPolygon('CS-_total_charge_current_battery') Or  IsNamedPolygon('VBAT-') Or  IsNamedPolygon('VBAT-') Or  IsNamedPolygon('VBAT-') Or  IsNamedPolygon('CS-_total_charge_current_battery') Or  IsNamedPolygon('48Vout2') Or  IsNamedPolygon('VBAT-') Or  IsNamedPolygon('CS-_total_charge_current_battery') Or  IsNamedPolygon('VBAT-') Or  IsNamedPolygon('48V2') Or  IsNamedPolygon('48Vout1') Or  IsNamedPolygon('5V') Or  IsNamedPolygon('48Vout2') Or  IsNamedPolygon('CS-_total_charge_current_battery') Or  IsNamedPolygon('5V') Or  IsNamedPolygon('CS-') Or  IsNamedPolygon('VBAT-') Or  IsNamedPolygon('5V') Or  IsNamedPolygon('VBAT-') Or  IsNamedPolygon('48Vout1') Or  IsNamedPolygon('CS-_total_discharge_current_bus') Or  IsNamedPolygon('48Vout1') Or  IsNamedPolygon('CS-') Or  IsNamedPolygon('5V') Or  IsNamedPolygon('48Vout2') Or  IsNamedPolygon('CS-_total_charge_current_battery') Or  IsNamedPolygon('48Vout1') Or  IsNamedPolygon('VBAT-') Or  IsNamedPolygon('48Vout2')] p5: connectstyle=Direct reliefconductorwidth=10 reliefentries=4 polygonreliefangle="90 Angle" airgapwidth=10
PolygonConnect PolygonConnect_27 [All vs IsNamedPolygon('VBAT-') Or  IsNamedPolygon('5V') Or  IsNamedPolygon('5V') Or  IsNamedPolygon('VBAT-') Or  IsNamedPolygon('VBAT-') Or  IsNamedPolygon('VBAT-') Or  IsNamedPolygon('VBAT-') Or  IsNamedPolygon('VBAT-') Or  IsNamedPolygon('CS-_total_discharge_current_bus') Or  IsNamedPolygon('48Vout1') Or  IsNamedPolygon('VBAT-') Or  IsNamedPolygon('VBAT-') Or  IsNamedPolygon('CS-_total_discharge_current_bus') Or  IsNamedPolygon('CS-_total_charge_current_battery') Or  IsNamedPolygon('CS-_total_discharge_current_bus') Or  IsNamedPolygon('5V') Or  IsNamedPolygon('VBAT-') Or  IsNamedPolygon('VBAT-') Or  IsNamedPolygon('5V') Or  IsNamedPolygon('VBAT-') Or  IsNamedPolygon('5V') Or  IsNamedPolygon('CS+_total_charge_current_battery') Or  IsNamedPolygon('VBAT-') Or  IsNamedPolygon('48Vout2') Or  IsNamedPolygon('CS-_total_charge_current_battery') Or  IsNamedPolygon('48Vout2') Or  IsNamedPolygon('48Vout2') Or  IsNamedPolygon('CS-') Or  IsNamedPolygon('VBAT-') Or  IsNamedPolygon('CS+_total_charge_current_battery') Or  IsNamedPolygon('CS-_total_discharge_current_bus') Or  IsNamedPolygon('5V') Or  IsNamedPolygon('CS-_total_charge_current_battery') Or  IsNamedPolygon('5V') Or  IsNamedPolygon('5V') Or  IsNamedPolygon('48Vout2') Or  IsNamedPolygon('48V2') Or  IsNamedPolygon('48VOUT1') Or  IsNamedPolygon('48Vout2') Or  IsNamedPolygon('48Vout2') Or  IsNamedPolygon('48Vout2') Or  IsNamedPolygon('CS-_total_discharge_current_bus') Or  IsNamedPolygon('5V') Or  IsNamedPolygon('CS-_total_discharge_current_bus') Or  IsNamedPolygon('48Vout1') Or  IsNamedPolygon('VBAT-') Or  IsNamedPolygon('CS-_total_charge_current_battery')] p6: connectstyle=Direct reliefconductorwidth=10 reliefentries=4 polygonreliefangle="90 Angle" airgapwidth=10
PolygonConnect PolygonConnect_26 [All vs IsNamedPolygon('48Vout2') Or  IsNamedPolygon('VBAT-') Or  IsNamedPolygon('VBAT-') Or  IsNamedPolygon('VBAT-') Or  IsNamedPolygon('5V') Or  IsNamedPolygon('CS-_total_discharge_current_bus') Or  IsNamedPolygon('CS-_total_charge_current_battery') Or  IsNamedPolygon('48Vout2') Or  IsNamedPolygon('48Vout1') Or  IsNamedPolygon('CS-_total_charge_current_battery') Or  IsNamedPolygon('5V') Or  IsNamedPolygon('CS+_total_charge_current_battery') Or  IsNamedPolygon('CS-_total_discharge_current_bus') Or  IsNamedPolygon('5V') Or  IsNamedPolygon('CS-_total_discharge_current_bus') Or  IsNamedPolygon('CS-_total_discharge_current_bus') Or  IsNamedPolygon('48Vout2') Or  IsNamedPolygon('VBAT-') Or  IsNamedPolygon('CS-_total_discharge_current_bus') Or  IsNamedPolygon('5V') Or  IsNamedPolygon('VBAT-') Or  IsNamedPolygon('5V') Or  IsNamedPolygon('VBAT-') Or  IsNamedPolygon('CS-_total_discharge_current_bus') Or  IsNamedPolygon('48Vout2') Or  IsNamedPolygon('48VOUT1') Or  IsNamedPolygon('48Vout1') Or  IsNamedPolygon('48Vout2') Or  IsNamedPolygon('5V') Or  IsNamedPolygon('VBAT-') Or  IsNamedPolygon('CS-_total_charge_current_battery') Or  IsNamedPolygon('48Vout2') Or  IsNamedPolygon('CS-') Or  IsNamedPolygon('VBAT-') Or  IsNamedPolygon('VBAT-') Or  IsNamedPolygon('5V') Or  IsNamedPolygon('5V') Or  IsNamedPolygon('48V2') Or  IsNamedPolygon('CS-_total_charge_current_battery') Or  IsNamedPolygon('VBAT-') Or  IsNamedPolygon('48Vout2') Or  IsNamedPolygon('CS+_total_charge_current_battery') Or  IsNamedPolygon('5V')] p7: connectstyle=Direct reliefconductorwidth=10 reliefentries=4 polygonreliefangle="90 Angle" airgapwidth=10
PolygonConnect PolygonConnect_25 [All vs IsNamedPolygon('CS-_total_discharge_current_bus') Or  IsNamedPolygon('VBAT-') Or  IsNamedPolygon('5V') Or  IsNamedPolygon('5V') Or  IsNamedPolygon('VBAT-') Or  IsNamedPolygon('CS-_total_charge_current_battery') Or  IsNamedPolygon('VBAT-') Or  IsNamedPolygon('5V') Or  IsNamedPolygon('CS-_total_discharge_current_bus') Or  IsNamedPolygon('5V') Or  IsNamedPolygon('CS-_total_charge_current_battery') Or  IsNamedPolygon('VBAT-') Or  IsNamedPolygon('CS-_total_discharge_current_bus') Or  IsNamedPolygon('48Vout2') Or  IsNamedPolygon('CS-_total_discharge_current_bus') Or  IsNamedPolygon('VBAT-') Or  IsNamedPolygon('VBAT-') Or  IsNamedPolygon('VBAT-') Or  IsNamedPolygon('CS-_total_discharge_current_bus') Or  IsNamedPolygon('48VOUT1') Or  IsNamedPolygon('CS+_total_charge_current_battery') Or  IsNamedPolygon('5V') Or  IsNamedPolygon('5V') Or  IsNamedPolygon('VBAT-') Or  IsNamedPolygon('48Vout2') Or  IsNamedPolygon('5V') Or  IsNamedPolygon('CS-_total_discharge_current_bus') Or  IsNamedPolygon('CS-_total_charge_current_battery') Or  IsNamedPolygon('48Vout2') Or  IsNamedPolygon('CS-_total_charge_current_battery') Or  IsNamedPolygon('48Vout2') Or  IsNamedPolygon('5V') Or  IsNamedPolygon('5V') Or  IsNamedPolygon('48Vout2') Or  IsNamedPolygon('CS+_total_charge_current_battery') Or  IsNamedPolygon('48V2') Or  IsNamedPolygon('VBAT-') Or  IsNamedPolygon('48Vout2')] p8: connectstyle=Direct reliefconductorwidth=10 reliefentries=4 polygonreliefangle="90 Angle" airgapwidth=10
PolygonConnect PolygonConnect_24 [All vs IsNamedPolygon('VBAT-') Or  IsNamedPolygon('VBAT-') Or  IsNamedPolygon('VBAT-') Or  IsNamedPolygon('48VOUT1') Or  IsNamedPolygon('VBAT-') Or  IsNamedPolygon('48VOUT2') Or  IsNamedPolygon('CS-_total_charge_current_battery') Or  IsNamedPolygon('VBAT-') Or  IsNamedPolygon('CS+_total_charge_current_battery') Or  IsNamedPolygon('VBAT-') Or  IsNamedPolygon('VBAT-') Or  IsNamedPolygon('VBAT-') Or  IsNamedPolygon('CS-_total_charge_current_battery') Or  IsNamedPolygon('VBAT-') Or  IsNamedPolygon('CS-_total_charge_current_battery') Or  IsNamedPolygon('48VOUT1') Or  IsNamedPolygon('AutoNaming') Or  IsNamedPolygon('VBAT-') Or  IsNamedPolygon('CS-_total_charge_current_battery') Or  IsNamedPolygon('48VOUT1') Or  IsNamedPolygon('VBAT-') Or  IsNamedPolygon('CS-_total_charge_current_battery') Or  IsNamedPolygon('48VOUT2') Or  IsNamedPolygon('48VOUT1') Or  IsNamedPolygon('12V') Or  IsNamedPolygon('VBAT-') Or  IsNamedPolygon('VBAT-') Or  IsNamedPolygon('CS+_total_charge_current_battery') Or  IsNamedPolygon('5V') Or  IsNamedPolygon('5V') Or  IsNamedPolygon('5V') Or  IsNamedPolygon('CS-_total_charge_current_battery') Or  IsNamedPolygon('CS-_total_charge_current_battery') Or  IsNamedPolygon('VBAT-') Or  IsNamedPolygon('VBAT-') Or  IsNamedPolygon('VBAT-') Or  IsNamedPolygon('5V') Or  IsNamedPolygon('VBAT-') Or  IsNamedPolygon('VBAT-') Or  IsNamedPolygon('48VOUT2') Or  IsNamedPolygon('VBAT-') Or  IsNamedPolygon('VBAT-') Or  IsNamedPolygon('VBAT-') Or  IsNamedPolygon('48VOUT1') Or  IsNamedPolygon('VBAT-') Or  IsNamedPolygon('CS+_total_charge_current_battery') Or  IsNamedPolygon('5V') Or  IsNamedPolygon('5V') Or  IsNamedPolygon('48Vout2') Or  IsNamedPolygon('CS-_total_charge_current_battery') Or  IsNamedPolygon('3V3') Or  IsNamedPolygon('CS-_total_discharge_current_bus') Or  IsNamedPolygon('CS-_total_discharge_current_bus') Or  IsNamedPolygon('CS-_total_discharge_current_bus') Or  IsNamedPolygon('CS-_total_discharge_current_bus') Or  IsNamedPolygon('CS-_total_discharge_current_bus') Or  IsNamedPolygon('48Vout2') Or  IsNamedPolygon('48Vout2') Or  IsNamedPolygon('5V') Or  IsNamedPolygon('12V') Or  IsNamedPolygon('48Vout2') Or  IsNamedPolygon('48Vout2') Or  IsNamedPolygon('48Vout2') Or  IsNamedPolygon('CS-_total_discharge_current_bus') Or  IsNamedPolygon('5V') Or  IsNamedPolygon('5V') Or  IsNamedPolygon('5V')] p9: connectstyle=Direct reliefconductorwidth=10 reliefentries=4 polygonreliefangle="90 Angle" airgapwidth=10
PolygonConnect PolygonConnect_23 [All vs IsNamedPolygon('5V') Or  IsNamedPolygon('12V') Or  IsNamedPolygon('CS+_total_charge_current_battery') Or  IsNamedPolygon('CS-_total_charge_current_battery') Or  IsNamedPolygon('5V') Or  IsNamedPolygon('VBAT-') Or  IsNamedPolygon('48VOUT1') Or  IsNamedPolygon('48VOUT1') Or  IsNamedPolygon('5V') Or  IsNamedPolygon('VBAT-') Or  IsNamedPolygon('VBAT-') Or  IsNamedPolygon('48Vout2') Or  IsNamedPolygon('VBAT-') Or  IsNamedPolygon('VBAT-') Or  IsNamedPolygon('48Vout2') Or  IsNamedPolygon('5V') Or  IsNamedPolygon('5V') Or  IsNamedPolygon('VBAT-') Or  IsNamedPolygon('CS-_total_discharge_current_bus') Or  IsNamedPolygon('VBAT-') Or  IsNamedPolygon('VBAT-') Or  IsNamedPolygon('48Vout2') Or  IsNamedPolygon('VBAT-') Or  IsNamedPolygon('CS-_total_charge_current_battery') Or  IsNamedPolygon('48VOUT2') Or  IsNamedPolygon('48Vout2') Or  IsNamedPolygon('CS-_total_discharge_current_bus') Or  IsNamedPolygon('VBAT-') Or  IsNamedPolygon('48Vout2') Or  IsNamedPolygon('CS-_total_charge_current_battery') Or  IsNamedPolygon('CS-_total_charge_current_battery') Or  IsNamedPolygon('5V') Or  IsNamedPolygon('48VOUT2') Or  IsNamedPolygon('CS-_total_charge_current_battery') Or  IsNamedPolygon('5V') Or  IsNamedPolygon('CS-_total_discharge_current_bus') Or  IsNamedPolygon('CS+_total_charge_current_battery') Or  IsNamedPolygon('CS-_total_discharge_current_bus') Or  IsNamedPolygon('48Vout2') Or  IsNamedPolygon('CS-_total_discharge_current_bus') Or  IsNamedPolygon('CS-_total_charge_current_battery') Or  IsNamedPolygon('5V') Or  IsNamedPolygon('CS-_total_discharge_current_bus') Or  IsNamedPolygon('VBAT-')] p10: connectstyle=Direct reliefconductorwidth=10 reliefentries=4 polygonreliefangle="90 Angle" airgapwidth=10
PolygonConnect PolygonConnect_22 [All vs IsNamedPolygon('5V') Or  IsNamedPolygon('VBAT-') Or  IsNamedPolygon('CS-_total_discharge_current_bus') Or  IsNamedPolygon('CS-_total_discharge_current_bus') Or  IsNamedPolygon('5V') Or  IsNamedPolygon('CS-_total_discharge_current_bus') Or  IsNamedPolygon('VBAT-') Or  IsNamedPolygon('48Vout2') Or  IsNamedPolygon('48Vout2') Or  IsNamedPolygon('48Vout2') Or  IsNamedPolygon('48VOUT2') Or  IsNamedPolygon('CS-_total_discharge_current_bus') Or  IsNamedPolygon('CS-_total_charge_current_battery') Or  IsNamedPolygon('48Vout2') Or  IsNamedPolygon('CS+_total_charge_current_battery') Or  IsNamedPolygon('12V') Or  IsNamedPolygon('CS-_total_discharge_current_bus') Or  IsNamedPolygon('48Vout2') Or  IsNamedPolygon('CS-_total_charge_current_battery') Or  IsNamedPolygon('48Vout2') Or  IsNamedPolygon('CS-_total_discharge_current_bus') Or  IsNamedPolygon('VBAT-') Or  IsNamedPolygon('48VOUT2') Or  IsNamedPolygon('48VOUT1') Or  IsNamedPolygon('VBAT-')] p11: connectstyle=Direct reliefconductorwidth=10 reliefentries=4 polygonreliefangle="90 Angle" airgapwidth=10
PolygonConnect PolygonConnect_21 [All vs IsNamedPolygon('CS+_total_charge_current_battery') Or  IsNamedPolygon('CS-_total_discharge_current_bus') Or  IsNamedPolygon('48Vout2') Or  IsNamedPolygon('CS-_total_discharge_current_bus') Or  IsNamedPolygon('48Vout2') Or  IsNamedPolygon('CS-_total_discharge_current_bus') Or  IsNamedPolygon('12V') Or  IsNamedPolygon('CS-_total_discharge_current_bus') Or  IsNamedPolygon('5V') Or  IsNamedPolygon('48Vout2') Or  IsNamedPolygon('48Vout2') Or  IsNamedPolygon('CS-_total_discharge_current_bus') Or  IsNamedPolygon('CS-_total_charge_current_battery') Or  IsNamedPolygon('5V') Or  IsNamedPolygon('48Vout2') Or  IsNamedPolygon('VBAT-') Or  IsNamedPolygon('48Vout2') Or  IsNamedPolygon('CS-_total_discharge_current_bus')] p12: connectstyle=Direct reliefconductorwidth=10 reliefentries=4 polygonreliefangle="90 Angle" airgapwidth=10
PolygonConnect PolygonConnect_20 [All vs IsNamedPolygon('48Vout2') Or  IsNamedPolygon('CS+_total_charge_current_battery') Or  IsNamedPolygon('48Vout2') Or  IsNamedPolygon('5V') Or  IsNamedPolygon('12V') Or  IsNamedPolygon('48Vout2') Or  IsNamedPolygon('48Vout2') Or  IsNamedPolygon('48Vout2') Or  IsNamedPolygon('48Vout2') Or  IsNamedPolygon('CS-_total_charge_current_battery') Or  IsNamedPolygon('VBAT-') Or  IsNamedPolygon('5V')] p13: connectstyle=Direct reliefconductorwidth=10 reliefentries=4 polygonreliefangle="90 Angle" airgapwidth=10
PolygonConnect PolygonConnect_19 [All vs IsNamedPolygon('VBAT-') Or  IsNamedPolygon('VBAT-') Or  IsNamedPolygon('VBAT-') Or  IsNamedPolygon('SW2') Or  IsNamedPolygon('VBAT_DISCH_IN') Or  IsNamedPolygon('VBAT_DISCH_IN') Or  IsNamedPolygon('VBAT_DISCH_IN') Or  IsNamedPolygon('CSB_DISCH') Or  IsNamedPolygon('VBAT-') Or  IsNamedPolygon('5V') Or  IsNamedPolygon('VBAT-') Or  IsNamedPolygon('SNGD') Or  IsNamedPolygon('VBAT-') Or  IsNamedPolygon('VBAT-') Or  IsNamedPolygon('SW2') Or  IsNamedPolygon('VBAT-') Or  IsNamedPolygon('VBAT-') Or  IsNamedPolygon('CSA_DISCH') Or  IsNamedPolygon('48V_DISCH_OUT') Or  IsNamedPolygon('VBAT_DISCH_IN') Or  IsNamedPolygon('VBAT-') Or  IsNamedPolygon('VBAT-') Or  IsNamedPolygon('48V_DISCH_OUT') Or  IsNamedPolygon('VBAT-') Or  IsNamedPolygon('CSA_DISCH') Or  IsNamedPolygon('5V') Or  IsNamedPolygon('VBAT-') Or  IsNamedPolygon('VBAT-') Or  IsNamedPolygon('48V_DISCH_OUT') Or  IsNamedPolygon('48V_DISCH_OUT') Or  IsNamedPolygon('VBAT-') Or  IsNamedPolygon('12V_AUX') Or  IsNamedPolygon('48V_DISCH_OUT') Or  IsNamedPolygon('VBAT_DISCH_IN') Or  IsNamedPolygon('VBAT_DISCH_IN') Or  IsNamedPolygon('VBAT-')] p14: connectstyle=Direct reliefconductorwidth=10 reliefentries=4 polygonreliefangle="90 Angle" airgapwidth=10
PolygonConnect PolygonConnect_18 [All vs IsNamedPolygon('SW2') Or  IsNamedPolygon('VBAT_DISCH_IN') Or  IsNamedPolygon('VBAT_DISCH_IN') Or  IsNamedPolygon('VBAT_DISCH_IN') Or  IsNamedPolygon('48V_DISCH_OUT') Or  IsNamedPolygon('VBAT_DISCH_IN') Or  IsNamedPolygon('VBAT-') Or  IsNamedPolygon('VBAT-') Or  IsNamedPolygon('VBAT-') Or  IsNamedPolygon('VBAT-') Or  IsNamedPolygon('VBAT-') Or  IsNamedPolygon('VBAT_DISCH_IN') Or  IsNamedPolygon('VBAT-') Or  IsNamedPolygon('CSA_DISCH') Or  IsNamedPolygon('VBAT-') Or  IsNamedPolygon('48V_DISCH_OUT') Or  IsNamedPolygon('48V_DISCH_OUT') Or  IsNamedPolygon('5V') Or  IsNamedPolygon('VBAT-') Or  IsNamedPolygon('VBAT-') Or  IsNamedPolygon('VBAT-') Or  IsNamedPolygon('VBAT-') Or  IsNamedPolygon('12V_AUX') Or  IsNamedPolygon('CSA_DISCH') Or  IsNamedPolygon('CSB_DISCH') Or  IsNamedPolygon('VBAT-') Or  IsNamedPolygon('VBAT-') Or  IsNamedPolygon('VBAT_DISCH_IN')] p15: connectstyle=Direct reliefconductorwidth=10 reliefentries=4 polygonreliefangle="90 Angle" airgapwidth=10
PolygonConnect PolygonConnect_17 [All vs IsNamedPolygon('VBAT-') Or  IsNamedPolygon('VBAT_DISCH_IN') Or  IsNamedPolygon('VBAT-') Or  IsNamedPolygon('VBAT_DISCH_IN') Or  IsNamedPolygon('CSA_DISCH') Or  IsNamedPolygon('VBAT_DISCH_IN') Or  IsNamedPolygon('VBAT_DISCH_IN') Or  IsNamedPolygon('VBAT-') Or  IsNamedPolygon('VBAT-') Or  IsNamedPolygon('48V_DISCH_OUT') Or  IsNamedPolygon('CSA_DISCH') Or  IsNamedPolygon('VBAT-') Or  IsNamedPolygon('VBAT_DISCH_IN') Or  IsNamedPolygon('VBAT-') Or  IsNamedPolygon('5V') Or  IsNamedPolygon('48V_DISCH_OUT') Or  IsNamedPolygon('VBAT-') Or  IsNamedPolygon('CSB_DISCH') Or  IsNamedPolygon('SW2') Or  IsNamedPolygon('VBAT-') Or  IsNamedPolygon('48V_DISCH_OUT') Or  IsNamedPolygon('VBAT-') Or  IsNamedPolygon('VBAT_DISCH_IN')] p16: connectstyle=Direct reliefconductorwidth=10 reliefentries=4 polygonreliefangle="90 Angle" airgapwidth=10
PolygonConnect PolygonConnect_16 [All vs IsNamedPolygon('VBAT-') Or  IsNamedPolygon('VBAT-') Or  IsNamedPolygon('CSA_DISCH') Or  IsNamedPolygon('48V_DISCH_OUT') Or  IsNamedPolygon('VBAT_DISCH_IN') Or  IsNamedPolygon('VBAT-') Or  IsNamedPolygon('VBAT-') Or  IsNamedPolygon('VBAT-') Or  IsNamedPolygon('VBAT-') Or  IsNamedPolygon('VBAT_DISCH_IN') Or  IsNamedPolygon('VBAT_DISCH_IN') Or  IsNamedPolygon('CSB_DISCH') Or  IsNamedPolygon('VBAT-') Or  IsNamedPolygon('VBAT_DISCH_IN') Or  IsNamedPolygon('VBAT_DISCH_IN') Or  IsNamedPolygon('VBAT-') Or  IsNamedPolygon('VBAT_DISCH_IN') Or  IsNamedPolygon('SW2') Or  IsNamedPolygon('CSA_DISCH') Or  IsNamedPolygon('VBAT-')] p17: connectstyle=Direct reliefconductorwidth=10 reliefentries=4 polygonreliefangle="90 Angle" airgapwidth=10
PolygonConnect PolygonConnect_15 [All vs IsNamedPolygon('CSA_DISCH') Or  IsNamedPolygon('VBAT-') Or  IsNamedPolygon('VBAT-') Or  IsNamedPolygon('48V_DISCH_OUT') Or  IsNamedPolygon('VBAT_DISCH_IN') Or  IsNamedPolygon('SW2') Or  IsNamedPolygon('VBAT_DISCH_IN') Or  IsNamedPolygon('VBAT-') Or  IsNamedPolygon('VBAT_DISCH_IN') Or  IsNamedPolygon('CSB_DISCH') Or  IsNamedPolygon('VBAT_DISCH_IN') Or  IsNamedPolygon('CSA_DISCH') Or  IsNamedPolygon('VBAT_DISCH_IN')] p18: connectstyle=Direct reliefconductorwidth=10 reliefentries=4 polygonreliefangle="90 Angle" airgapwidth=10
PolygonConnect PolygonConnect_14 [All vs IsNamedPolygon('SW2') Or  IsNamedPolygon('48V_DISCH_OUT') Or  IsNamedPolygon('VBAT-') Or  IsNamedPolygon('VBAT-') Or  IsNamedPolygon('CSA_DISCH') Or  IsNamedPolygon('CSB_DISCH')] p19: connectstyle=Direct reliefconductorwidth=10 reliefentries=4 polygonreliefangle="90 Angle" airgapwidth=10
PolygonConnect PolygonConnect_13 [All vs IsNamedPolygon('VBAT-') Or  IsNamedPolygon('48V_DISCH_OUT') Or  IsNamedPolygon('VBAT-') Or  IsNamedPolygon('CSB_DISCH') Or  IsNamedPolygon('CSA_DISCH')] p20: connectstyle=Direct reliefconductorwidth=10 reliefentries=4 polygonreliefangle="90 Angle" airgapwidth=10
PolygonConnect PolygonConnect_12 [All vs IsNamedPolygon('48V_DISCH_OUT') Or  IsNamedPolygon('VBAT-') Or  IsNamedPolygon('VBAT-')] p21: connectstyle=Direct reliefconductorwidth=10 reliefentries=4 polygonreliefangle="90 Angle" airgapwidth=10
PolygonConnect PolygonConnect_11 [All vs IsNamedPolygon('GND') Or  IsNamedPolygon('D101_2') Or  IsNamedPolygon('V+') Or  IsNamedPolygon('GND') Or  IsNamedPolygon('C128_1') Or  IsNamedPolygon('J2_2') Or  IsNamedPolygon('CS') Or  IsNamedPolygon('V+') Or  IsNamedPolygon('GND') Or  IsNamedPolygon('J2_2') Or  IsNamedPolygon('PGND') Or  IsNamedPolygon('12V') Or  IsNamedPolygon('PGND') Or  IsNamedPolygon('PGND') Or  IsNamedPolygon('V+') Or  IsNamedPolygon('V+') Or  IsNamedPolygon('D101_2') Or  IsNamedPolygon('CS') Or  IsNamedPolygon('GND')] p22: connectstyle=Direct reliefconductorwidth=10 reliefentries=4 polygonreliefangle="90 Angle" airgapwidth=10
PolygonConnect PolygonConnect_10 [All vs IsNamedPolygon('GND') Or  IsNamedPolygon('C128_1') Or  IsNamedPolygon('GND') Or  IsNamedPolygon('J2_2') Or  IsNamedPolygon('GND') Or  IsNamedPolygon('D101_2') Or  IsNamedPolygon('J2_2') Or  IsNamedPolygon('V+') Or  IsNamedPolygon('PGND') Or  IsNamedPolygon('CS') Or  IsNamedPolygon('V+')] p23: connectstyle=Direct reliefconductorwidth=10 reliefentries=4 polygonreliefangle="90 Angle" airgapwidth=10
PolygonConnect PolygonConnect_9 [All vs IsNamedPolygon('J2_2') Or  IsNamedPolygon('GND') Or  IsNamedPolygon('8V5') Or  IsNamedPolygon('V+') Or  IsNamedPolygon('R117_1') Or  IsNamedPolygon('PGND') Or  IsNamedPolygon('PGND') Or  IsNamedPolygon('Drv') Or  IsNamedPolygon('V+') Or  IsNamedPolygon('V+') Or  IsNamedPolygon('C128_1') Or  IsNamedPolygon('GND') Or  IsNamedPolygon('GND') Or  IsNamedPolygon('J2_2') Or  IsNamedPolygon('PGND')] p24: connectstyle=Direct reliefconductorwidth=10 reliefentries=4 polygonreliefangle="90 Angle" airgapwidth=10
PolygonConnect PolygonConnect_8 [All vs IsNamedPolygon('8V5') Or  IsNamedPolygon('J2_2') Or  IsNamedPolygon('PGND') Or  IsNamedPolygon('GND') Or  IsNamedPolygon('GND') Or  IsNamedPolygon('V+') Or  IsNamedPolygon('J2_2') Or  IsNamedPolygon('V+') Or  IsNamedPolygon('C128_1') Or  IsNamedPolygon('V+') Or  IsNamedPolygon('PGND') Or  IsNamedPolygon('J2_2') Or  IsNamedPolygon('J2_2') Or  IsNamedPolygon('R117_1')] p25: connectstyle=Direct reliefconductorwidth=10 reliefentries=4 polygonreliefangle="90 Angle" airgapwidth=10
PolygonConnect PolygonConnect_7 [All vs IsNamedPolygon('J2_2') Or  IsNamedPolygon('J2_2') Or  IsNamedPolygon('J2_2') Or  IsNamedPolygon('C128_1') Or  IsNamedPolygon('J2_2')] p26: connectstyle=Direct reliefconductorwidth=10 reliefentries=4 polygonreliefangle="90 Angle" airgapwidth=10
PolygonConnect PolygonConnect_6 [All vs IsNamedPolygon('J2_2')] p27: connectstyle=Direct reliefconductorwidth=10 reliefentries=4 polygonreliefangle="90 Angle" airgapwidth=10
PolygonConnect PolygonConnect_5 [All vs IsNamedPolygon('GND') Or  IsNamedPolygon('Vout') Or  IsNamedPolygon('Bottom Layer-SW') Or  IsNamedPolygon('GND') Or  IsNamedPolygon('C1_1') Or  IsNamedPolygon('Q1_3') Or  IsNamedPolygon('J2_2') Or  IsNamedPolygon('GND') Or  IsNamedPolygon('J2_2') Or  IsNamedPolygon('GND') Or  IsNamedPolygon('Vout') Or  IsNamedPolygon('Top Layer-SW') Or  IsNamedPolygon('Q1_3') Or  IsNamedPolygon('GND') Or  IsNamedPolygon('J2_2') Or  IsNamedPolygon('J2_2') Or  IsNamedPolygon('GND') Or  IsNamedPolygon('GND') Or  IsNamedPolygon('GND') Or  IsNamedPolygon('GND') Or  IsNamedPolygon('GND')] p28: connectstyle=Direct reliefconductorwidth=10 reliefentries=4 polygonreliefangle="90 Angle" airgapwidth=10
PolygonConnect PolygonConnect_4 [All vs IsNamedPolygon('GND') Or  IsNamedPolygon('Bottom Layer-SW') Or  IsNamedPolygon('C1_1') Or  IsNamedPolygon('Top Layer-SW') Or  IsNamedPolygon('GND') Or  IsNamedPolygon('GND') Or  IsNamedPolygon('GND') Or  IsNamedPolygon('Q1_3') Or  IsNamedPolygon('Vout') Or  IsNamedPolygon('Q1_3') Or  IsNamedPolygon('Vout')] p29: connectstyle=Direct reliefconductorwidth=10 reliefentries=4 polygonreliefangle="90 Angle" airgapwidth=10
PolygonConnect PolygonConnect_3 [All vs IsNamedPolygon('Q1_3') Or  IsNamedPolygon('Q1_3') Or  IsNamedPolygon('Top Layer-SW') Or  IsNamedPolygon('C1_1') Or  IsNamedPolygon('Bottom Layer-SW')] p30: connectstyle=Direct reliefconductorwidth=10 reliefentries=4 polygonreliefangle="90 Angle" airgapwidth=10
PolygonConnect PolygonConnect_2 [All vs IsNamedPolygon('Top Layer-SW') Or  IsNamedPolygon('Bottom Layer-SW')] p31: connectstyle=Direct reliefconductorwidth=10 reliefentries=4 polygonreliefangle="90 Angle" airgapwidth=10
PolygonConnect PolygonConnect_1 [All vs IsNamedPolygon('Bottom Layer-SW') Or  IsNamedPolygon('Top Layer-SW')] p32: thpad.connectstyle=Direct thpad.reliefconductorwidth=10 thpad.reliefentries=4 thpad.polygonreliefangle="90 Angle" thpad.airgapwidth=10 smdpad.connectstyle=Direct smdpad.reliefconductorwidth=10 smdpad.reliefentries=4 smdpad.polygonreliefangle="90 Angle" smdpad.airgapwidth=10 via.connectstyle=Relief via.reliefconductorwidth=10 via.reliefentries=4 via.polygonreliefangle="90 Angle" via.airgapwidth=10
PolygonConnect [All] p33: connectstyle=Relief reliefconductorwidth=10 reliefentries=4 polygonreliefangle="90 Angle" airgapwidth=10
RoutingVias ThermalPadVias [IsVia and InAnyComponent] p1: holewidth=7.87 width=19.68 viastyle="Through Hole" minholewidth=7.87 minwidth=19.68 maxholewidth=25 maxwidth=36
RoutingVias [All] p2: holewidth=10 width=20 viastyle="Through Hole" minholewidth=7.87 minwidth=20 maxholewidth=40 maxwidth=65
SilkToBoardRegionClearance [Not ((IsComment or IsDesignator) And (Hide <> 'False')) and not InRegion(1000,500,4000,800)] p1:
SilkToSilkClearance SilkToSilkClearance_Pb-FreeLogo [(HasFootprint('Pb-Free_Overlay_Medium') OR HasFootprint('Pb-Free_Overlay_Small')) vs (HasFootprint('Pb-Free_Overlay_Medium') OR HasFootprint('Pb-Free_Overlay_Small'))] p1: silktosilkclearance=0
SilkToSilkClearance [All] p2: silktosilkclearance=4
SilkToSolderMaskClearance SilkToComponentPadClearance [(IsPad or IsFill or IsRegion) and InAnycomponent] p1: minsilkscreentomaskgap=5 clearancetoexposedcopper=TRUE
SilkToSolderMaskClearance "Silk to Solder Mask Opening" [All] p2: minsilkscreentomaskgap=4 clearancetoexposedcopper=FALSE
SolderMaskExpansion [All] p1: expansion=1.97
Width [All] p1: maxlimit=100 minlimit=6 preferedwidth=10 checkconnectedcopper=TRUE
15 further rules are at their usual default settings.

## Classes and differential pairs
component class Header: J201 J400
component class PMP23421_buffer: C1 C2 C3 C4 C5 C400 C401 C402 C403 C404 C405 C406 C407 C408 C409 C410 C411 J400 R2 R400 R401 R402 R403 R404 R405 R406 R407 R408 R409 R410 R411 R412 R413 R414 R415 R416 R417 R418 R419 R420 R421 R422 R423 R424 R425 R426 R427 R428 R429 R430 R431 U400 U401 U402 U403 U404 U405
component class PMP23421_Control: 5V 12Vs 200 C200 C201 C202 C203 C204 C205 C206 C207 C208 C209 C210 C211 C212 C213 C214 C215 C216 C217 C218 C219 C220 C221 C222 C223 C224 C225 CC203 J200 J201 J202 R200 R201 R202 R203 R204 R205 R206 R207 R208 R209 R210 R211 R212 R213 R214 R215 R216 R217 R218 R219 R220 R221 R222 R223 R224 R225 R226 R227 R228 R229 R230 R231 R232 SGND SGND200 U200 U201 U202 U203
component class PMP23421_ORING_N_CS: C300 C301 C302 C303 C304 C305 C306 C307 C308 C309 C310 C311 C312 C313 C314 C315 J300 J301 J302 J303 J304 J305 J306 Q300 Q301 Q302 R300 R301 R302 R303 T300 T301 T302 T303 TP300 TP301 TP302 TP303 TP304 TP305 TP306 TP307 TP308 TP309 TP310 TP311 TP312 TP313 TP314 TP315 TP316 TP317 TP318 TP319 TP320 TP321 TP322 TP323 TP324 TP325 TP326 TP327 TP328 TP329 TP330 TP331 TP332 TP333 TP334 TP335 TP336 TP337 TP338 TP339 TP340 TP341 TP342 TP343 TP344 TP345 TP346 TP347 TP348 TP349 TP350 TP351 TP352 TP353 TP354 TP355 U300

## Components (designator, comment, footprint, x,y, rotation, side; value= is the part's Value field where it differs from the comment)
5V "5000" Keystone5000 2491.77,2524.52 r90 top
12Vs "5000" Keystone5000 2613.78,2894.01 r90 top
C200 "C0603C100F5GAC7867" 0603 2370,419.75 r180 bottom value=10pF
C201 "C0603C100F5GAC7867" 0603 2370,491.23 r180 bottom value=10pF
C202 "C0603C100F5GAC7867" 0603 2210,375 r0 bottom value=10pF
C203 "C0603C100F5GAC7867" 0603 2210,430 r0 bottom value=10pF
C204 "C0603C100F5GAC7867" 0603 2210,540 r0 bottom value=10pF
C205 "C0603C100F5GAC7867" 0603 2370,562.7 r180 bottom value=10pF
C206 "C0603C100F5GAC7867" 0603 2370,634.18 r180 bottom value=10pF
C207 "GRM32ER61C476KE15L" 1210_270 2507.15,2784.73 r270 bottom value=47uF
C208 "C0805C105K3RACTU" 0805_HV 2354.41,2731.3 r0 bottom value=1uF
C209 "CL21A226KQQNNNE" 0805_HV 2361.16,2432.36 r180 bottom value=22uF
C210 "GRM155R70J104KA01D" 0402 2594.82,2392.67 r180 top value=0.1uF
C211 "C0402C103K4RACTU" 0402 2215.07,2518.01 r180 bottom value=0.01uF
C212 "GRM155R70J104KA01D" 0402 2590.88,2157.33 r180 top value=0.1uF
C213 "GRM155R70J104KA01D" 0402 2594.82,2450.68 r180 top value=0.1uF
C214 "06035A680JAT2A" 0603 1940,-2695 r270 bottom value=68pF
C215 "GRM1555C1H470FA01D" 0402 1875,-2585.06 r180 bottom value=47pF
C216 "GRM1555C1H470FA01D" 0402 1855.5,-2795 r180 bottom value=47pF
C217 "C1608X7R1C105K080AC" 0603 1700.27,-2690 r270 bottom value=1uF
C218 "GRM155R70J104KA01D" 0402 1755,-2700 r270 bottom value=0.1uF
C219 "C0603C100F5GAC7867" 0603 2210,485 r0 bottom value=10pF
C220 "06035A680JAT2A" 0603 1209.61,915.43 r0 top value=68pF
C221 "GRM1555C1H470FA01D" 0402 1116.93,895 r90 top value=47pF
C222 "GRM1555C1H470FA01D" 0402 1344.99,953.64 r90 top value=47pF
C223 "C1608X7R1C105K080AC" 0603 1088.23,1015.07 r270 top value=1uF
C224 "GRM155R70J104KA01D" 0402 1188.66,1130 r0 top value=0.1uF
C225 "C0603C100F5GAC7867" 0603 2210,595.65 r0 bottom value=10pF
C300 "GRJ31CC72A475KE01L" 1206_180 1480.24,465 r270 bottom value=4.7uF
C301 "63PFV22M6.3X8" SM_RADIAL_D 485,-1650 r270 top value=22uF
C302 "63PFV22M6.3X8" SM_RADIAL_D 1255,-1650 r270 top value=22uF
C303 "63PFV22M6.3X8" SM_RADIAL_D 1801.81,-1650 r270 top value=22uF
C304 "63PFV22M6.3X8" SM_RADIAL_D 2076.76,-1650 r270 top value=22uF
C305 "63PFV22M6.3X8" SM_RADIAL_D 386.77,495 r270 top value=22uF
C306 "63PFV22M6.3X8" SM_RADIAL_D 660,495 r270 top value=22uF
C307 "63PFV22M6.3X8" SM_RADIAL_D 1370,365 r270 top value=22uF
C308 "63PFV22M6.3X8" SM_RADIAL_D 1095,365 r270 top value=22uF
C309 "63PFV22M6.3X8" SM_RADIAL_D 470,-2330 r90 top value=22uF
C310 "63PFV22M6.3X8" SM_RADIAL_D 386.77,-240 r90 top value=22uF
C311 "63PFV22M6.3X8" SM_RADIAL_D 660,-240 r90 top value=22uF
C312 "63PFV22M6.3X8" SM_RADIAL_D 1240,-2330 r90 top value=22uF
C313 "GRJ31CC72A475KE01L" 1206_180 2035,-2270 r90 top value=4.7uF
C314 "12061C104JAT2A" 1206 2489.13,-2537.98 r0 bottom value=0.1uF
C315 "63PFV22M6.3X8" SM_RADIAL_D 1370,-235 r90 top value=22uF
C400 "GRM155R70J104KA01D" 0402 1703.38,3180.71 r90 top value=0.1uF
C401 "12061C104JAT2A" 1206 1744.72,3381.25 r0 top value=0.1uF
